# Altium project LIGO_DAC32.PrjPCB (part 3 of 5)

## Sheet LD32_XADC.SchDoc: XADC
size B; SheetNumber: 10; SheetTotal: 17; SPICEModelCacheGFFRXQKT: <root> / <DocumentId>GFFRXQKT</DocumentId> / <CacheFrame Number="0"> / <Model Name="op284f" Kind="CKT"> / <Text>* OP284F SPICE Macro-model              11/95 / Rev. B / *                                       ARG / ADSC / * / * Revision History: / * / *     Rev. B / * Changed the short-circuit output current limit from +/- 7.5mA / * to +/- 6.5mA to reflect final data sheet limits. / * / * Changed Vos spec to conform to final data sheet value of / * 125uV, up from 50uV. / * / * / * This version of the OP284 model simulates the worst-case / * parameters of the 'F' grade.  The worst-case parameters / * used correspond to those in the data sheet. / * / * Copyright 1993 by Analog Devices / * / * Refer to "README.DOC" file for License Statement. Use of this model / * indicates your acceptance of the terms and provisions in the License / * Statement. / * / * Node assignments / *                non-inverting input / *                ¦   inverting input / *                ¦   ¦   positive supply / *                ¦   ¦   ¦   negative supply / *                ¦   ¦   ¦   ¦   output / *                ¦   ¦   ¦   ¦   ¦ / .SUBCKT OP284F   1   2   99  50  45 / * / * INPUT STAGE / * / Q1   5    2    3    QIN 1 / Q2   6    11   3    QIN 1 / Q3   7    2    4    QIP 1 / Q4   8    11   4    QIP 1 / DC1  2    11   DC / DC2  11   2    DC / Q5   4    9    99   QIP 1 / Q6   9    9    99   QIP 1 / Q7   3    10   50   QIN 1 / Q8   10   10   50   QIN 1 / R1   99   5    4E3 / R2   99   6    4E3 / R3   7    50   4E3 / R4   8    50   4E3 / IREF 9    10   50.5E-6 / EOS  1    11   POLY(2) (22,98) (14,98) -125E-6 501.2E-3 1 / IOS  2    1    25E-9 / CIN  1    2    2E-12 / GN1  98   1    17 98 1E-3 / GN2  98   2    23 98 1E-3 / * / * VOLTAGE NOISE SOURCE WITH FLICKER NOISE / * / VN1  13   98   DC 2 / VN2  98   15   DC 2 / DN1  13   14   DEN / DN2  14   15   DEN / * / * CURRENT NOISE SOURCE WITH FLICKER NOISE / * / VN3  16   98   DC 2 / VN4  98   18   DC 2 / DN3  16   17   DIN / DN4  17   18   DIN / * / * 2ND CURRENT NOISE SOURCE WITH FLICKER NOISE / * / VN5  19   98   DC 2 / VN6  98   24   DC 2 / DN5  19   23   DIN / DN6  23   24   DIN / * / * GAIN STAGE / * / EREF 98   0    POLY(2) (99,0) (50,0) 0 0.5 0.5 / G1   98   20   POLY(2) (6,5) (8,7) 0 0.5E-3 0.5E-3 / R9   20   98   1E3 / * / * COMMON MODE STAGE WITH ZERO AT 5KHZ / * / ECM  98   21   POLY(2) (1,98) (2,98) 0 0.5 0.5 / R10  21   22   1 / R11  22   98   100E-6 / C4   21   22   31.756E-6 / * / * NEGATIVE ZERO AT 20MHZ / * / E1   27   98   20 98 1 / R17  27   28   1 / R18  28   98   1E-6 / C8   25   26   7.958E-9 / ENZ  25   98   27 28 1 / VNZ  26   98   DC 0 / FNZ  27   28   VNZ -1 / * / * POLE AT 40MHZ / * / G4   98   29   28 98 1E6 / R19  29   98   1 / C9   29   98   3.979E-9 / * / * POLE AT 40MHZ / * / G5   98   30   29 98 1 / R20  30   98   1 / C10  30   98   3.979E-9 / * / * OUTUT STAGE / * / ISY  99   50   0.526E-3 / GIN  50   31   POLY(1) (30,98) 0.862574E-6 511.855E-6 / RIN  31   50   2.75E6 / VB   99   32   0.7 / Q11  32   31   33   QON 1 / R21  33   34   4.5E3 / I1   34   50   50E-6 / R22  99   35   6E3 / Q12  36   36   35   QOP 1 / I2   36   50   50E-6 / R23  99   37   2.6E3 / R24  34   38   5E3 / Q13  39   36   37   QOP 1 / Q14  39   38   40   QON 1.5 / R25  40   50   40 / Q15  39   39   41   QON 1 / R26  41   42   1E3 / R27  99   43   220 / Q16  44   44   43   QOP 1.5 / Q17  44   39   42   QON 1 / R28  42   50   2E3 / VSCP 99   97   DC 0 / FSCP 46   99   VSCP 1 / RSCP 46   99   125 / Q20  44   46   99   QOP 1 / Q18  45   44   97   QOP 4.5 / Q19  45   34   51   QON 4.5 / VSCN 51   50   DC 0 / FSCN 50   47   VSCN 1 / RSCN 47   50   122 / Q21  34   47   50   QON 1 / CC2  31   45   20E-12 / CF1  31   34   15E-12 / CF2  31   42   15E-12 / CO1  34   45   15E-12 / CO2  42   45   5E-12 / D3   45   99   DX / D4   50   45   DX / .MODEL DC D(IS=130E-21) / .MODEL DX D() / .MODEL DEN D(RS=100 KF=12E-15 AF=1) / .MODEL DIN D(RS=5.358 KF=56E-15 AF=1) / .MODEL QIN NPN(BF=250 VA=200 IS=0.5E-16) / .MODEL QIP PNP(BF=60 VA=100 IS=0.5E-16) / .MODEL QON NPN(BF=200 VA=200 IS=0.5E-16 RC=140) / .MODEL QOP PNP(BF=200 VA=200 IS=0.5E-16 RC=210) / .ENDS</Text> / </Model> / </CacheFrame> / </root>
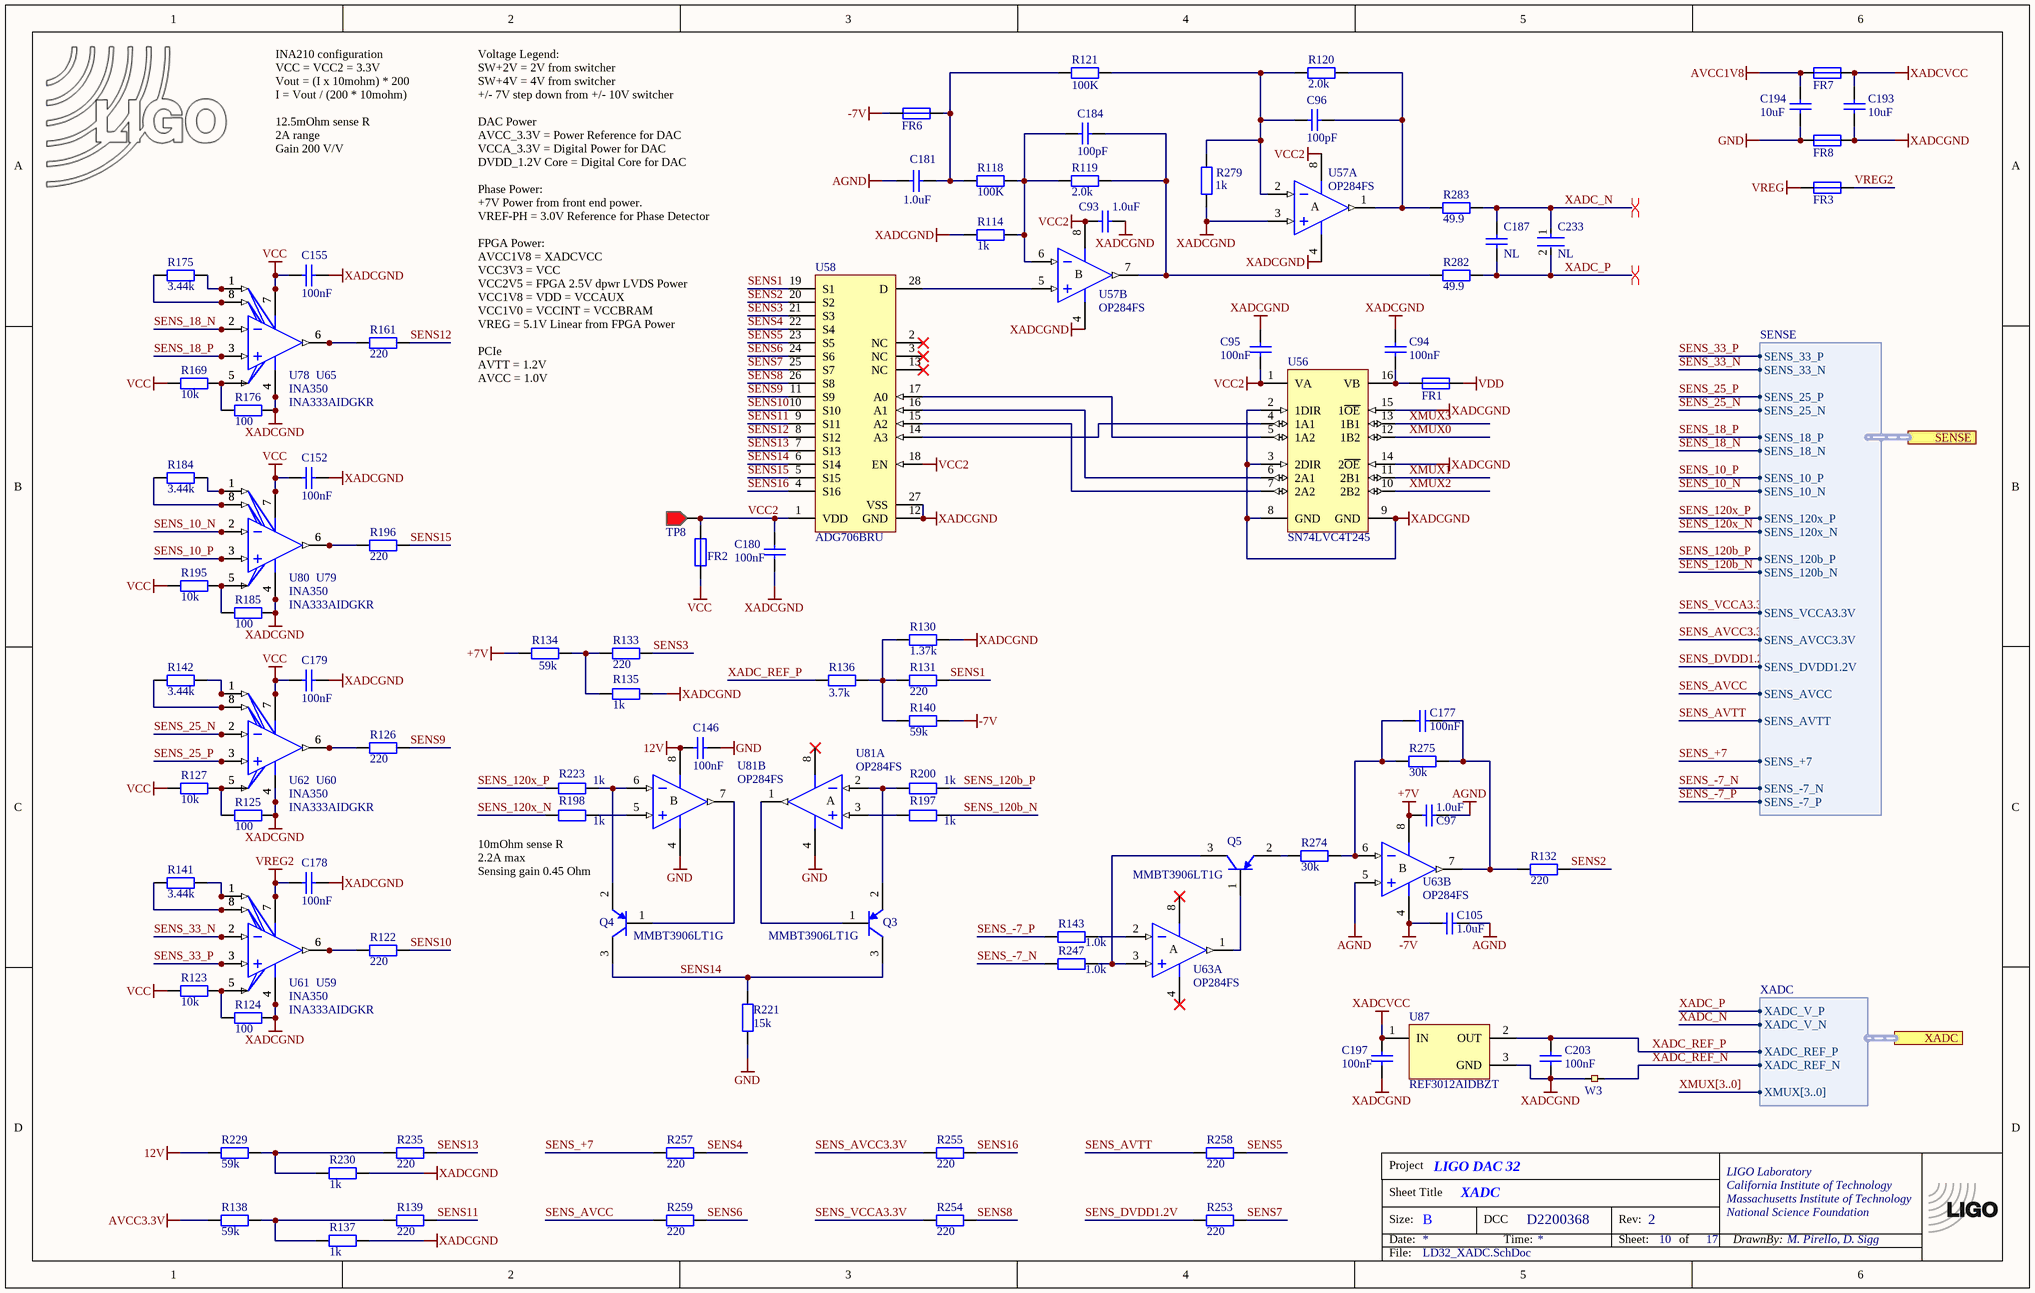
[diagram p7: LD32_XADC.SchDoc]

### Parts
(Parts that share a designator on the sheet are numbered #1, #2 ... from top to bottom, then left to right.)
*  TitleBlock  (value not drawn)  (graphical)
C93  1.0uF  [CC1005-0402]
C94  100nF  [CC1005-0402]
C95  100nF  [CC1005-0402]
C96  100pF  [CC1005-0402]
C97  1.0uF  [CC1608-0603]
C105  1.0uF  [CC1608-0603]
C146  100nF  [CC1005-0402]
C152  100nF  [CC1608-0603]
C155  100nF  [CC1608-0603]
C177  100nF  [CC1005-0402]
C178  100nF  [CC1608-0603]
C179  100nF  [CC1608-0603]
C180  100nF  [CC1005-0402]
C181  1.0uF  [CC1005-0402]
C184  100pF  [CC1005-0402]
C187  NL  [CC1005-0402]
C193  10uF  [CC2013-0805]
C194  10uF  [CC2013-0805]
C197  100nF  [CC1005-0402]
C203  100nF  [CC1005-0402]
C233  NL  [FP-CL03-IPC_B]
FR1  BLM31PG121  [CC3216-1206]  (value not drawn)
FR2  BLM31PG121  [CC3216-1206]  (value not drawn)
FR3  BLM31PG121  [CC3216-1206]  (value not drawn)
FR6  BLM31PG121  [CC3216-1206]  (value not drawn)
FR7  BLM31PG121  [CC3216-1206]  (value not drawn)
FR8  BLM31PG121  [CC3216-1206]  (value not drawn)
LOGO4#1  LIGO logo  [LIGO_LOGO]  (value not drawn)  (graphical)
Q3  MMBT3906LT1G  [ONSC-SOT-23-3-318-08_V]
Q4  MMBT3906LT1G  [ONSC-SOT-23-3-318-08_V]
Q5  MMBT3906LT1G  [ONSC-SOT-23-3-318-08_V]
R114  1k  [CR1608-0603]
R118  100K  [CR1005-0402]
R119  2.0k  [CR1005-0402]
R120  2.0k  [CR1005-0402]
R121  100K  [CR1005-0402]
R122  220  [CR1608-0603]
R123  10k  [CR1608-0603]
R124  100  [CR1608-0603]
R125  100  [CR1608-0603]
R126  220  [CR1608-0603]
R127  10k  [CR1608-0603]
R130  1.37k  [CR1608-0603]
R131  220  [CR1608-0603]
R132  220  [CR1608-0603]
R133  220  [CR1608-0603]
R134  59k  [CR1608-0603]
R135  1k  [CR1608-0603]
R136  3.7k  [CR1608-0603]
R137  1k  [CR1608-0603]
R138  59k  [CR1608-0603]
R139  220  [CR1608-0603]
R140  59k  [CR1608-0603]
R141  3.44k  [CR1608-0603]
R142  3.44k  [CR1608-0603]
R143  1.0k  [CR1005-0402]
R161  220  [CR1608-0603]
R169  10k  [CR1608-0603]
R175  3.44k  [CR1608-0603]
R176  100  [CR1608-0603]
R184  3.44k  [CR1608-0603]
R185  100  [CR1608-0603]
R195  10k  [CR1608-0603]
R196  220  [CR1608-0603]
R197  1k  [CR0603-0201]
R198  1k  [CR0603-0201]
R200  1k  [CR0603-0201]
R221  15k  [CR1608-0603]
R223  1k  [CR0603-0201]
R229  59k  [CR1608-0603]
R230  1k  [CR1608-0603]
R235  220  [CR1608-0603]
R247  1.0k  [CR1005-0402]
R253  220  [CR1608-0603]
R254  220  [CR1608-0603]
R255  220  [CR1608-0603]
R257  220  [CR1608-0603]
R258  220  [CR1608-0603]
R259  220  [CR1608-0603]
R274  30k  [CR1005-0402]
R275  30k  [CR1005-0402]
R279  1k  [CR1608-0603]
R282  49.9  [CR1005-0402]
R283  49.9  [CR1005-0402]
TP8  Testpoint  [TP1-RED]  (value not drawn)
U56  SN74LVC4T245  [TSSOP16]
U57  OP284FS  [SO-8_N]  (parts A,B of 2)
U58  ADG706BRU  [ADI-RU-28_M]
U59  INA333AIDGKR  [DGK0008A_N]
U60  INA333AIDGKR  [DGK0008A_N]
U61  INA350  [FP-RJ-8-IPC_B]
U62  INA350  [FP-RJ-8-IPC_B]
U63  OP284FS  [SO-8_N]  (parts A,B of 2)
U65  INA333AIDGKR  [DGK0008A_N]
U78  INA350  [FP-RJ-8-IPC_B]
U79  INA333AIDGKR  [DGK0008A_N]
U80  INA350  [FP-RJ-8-IPC_B]
U81  OP284FS  [SO-8_N]  (parts A,B of 2)
U87  REF3012AIDBZT  [DBZ0003A_L]
W3  NL  [NETTIE1_SMDTOP]  (value not drawn)  (net tie, no BOM)

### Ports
SENSE (harness SENSE), XADC (harness XADC)

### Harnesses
XADC: XADC_REF_P, XADC_V_N, XADC_V_P, XMUX[3..0], XADC_REF_N
SENSE: SENS_33_P, SENS_33_N, SENS_25_P, SENS_25_N, SENS_18_P, SENS_18_N, SENS_10_P, SENS_10_N, SENS_120x_P, SENS_120x_N, SENS_120b_P, SENS_120b_N, SENS_VCCA3.3V, SENS_AVCC3.3V, SENS_DVDD1.2V, SENS_+7, SENS_-7_P, SENS_AVTT, SENS_AVCC, SENS_-7_N

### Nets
12V: C146.1 R229.1 U81.8(V+)
+7V: C97.2 R134.1 U63.8(V+)
-7V: C105.2 FR6.1 R140.2 R143.1 U63.4(V-) ; port SENSE.SENS_-7_P  [also labelled SENS_-7_P]
AGND: C97.1 C105.1 C181.1 U63.5(IN+)
AVCC1V8: C194.1 FR7.1
AVCC3.3V: R138.1
GND: C146.2 C194.2 FR8.1 R221.1 U81.4(V-)
SENS_10_N: U79.2(VIN-) U80.2(IN+) ; port SENSE.SENS_10_N  [project net VCC1V0]
SENS_18_N: FR1.2 U65.2(VIN-) U78.2(IN+) ; port SENSE.SENS_18_N  [also labelled VDD]  [project net VCCAUX]
SENS_25_N: U60.2(VIN-) U62.2(IN+) ; port SENSE.SENS_25_N  [project net VCC2V5]
VCC: C152.1 C155.1 C179.1 FR2.1 R123.1 R127.1 R169.1 R195.1 U59.2(VIN-) U60.7(V+) U61.2(IN+) U62.7(V+) U65.7(V+) U78.7(V+) U79.7(V+) U80.7(V+) ; port SENSE.SENS_33_N  [also labelled SENS_33_N]
VCC2: C93.1 C95.2 C180.1 FR2.2 TP8.1 U56.1(VA) U57.8(V+) U58.1(VDD) U58.18(EN)
VREG: FR3.1
VREG2: C178.1 FR3.2 U59.7(V+) U61.7(V+)
XADCGND: C93.2 C94.1 C95.1 C152.2 C155.2 C178.2 C179.2 C180.2 C193.2 C197.2 C203.2 FR8.2 R114.1 R124.2 R125.2 R130.2 R135.2 R137.2 R176.2 R185.2 R230.2 R279.1 U56.2(1DIR) U56.3(2DIR) U56.8(GND) U56.9(GND) U56.14(2~{OE}) U56.15(1~{OE}) U57.3(IN+) U57.4(V-) U58.12(GND) U58.27(VSS) U59.4(V-) U60.4(V-) U61.4(V-) U62.4(V-) U65.4(V-) U78.4(V-) U79.4(V-) U80.4(V-) U87.3(GND) W3.1
XADCVCC: C193.1 C197.1 FR7.2 U87.1(IN)
SENS1: R131.2 U58.19(S1)
SENS2: R132.2 U58.20(S2)
SENS3: R133.2 U58.21(S3)
SENS4: R257.2 U58.22(S4)
SENS5: R258.2 U58.23(S5)
SENS6: R259.2 U58.24(S6)
SENS7: R253.2 U58.25(S7)
SENS8: R254.2 U58.26(S8)
SENS9: R126.2 U58.11(S9)
SENS10: R122.2 U58.10(S10)
SENS11: R139.2 U58.9(S11)
SENS12: R161.2 U58.8(S12)
SENS13: R235.2 U58.7(S13)
SENS14: Q3.3(C) Q4.3(C) R221.2 U58.6(S14)
SENS15: R196.2 U58.5(S15)
SENS16: R255.2 U58.4(S16)
SENS_10_P: U79.3(VIN+) U80.3(IN-) ; port SENSE.SENS_10_P  [project net SENSE.SENS_10_P]
SENS_18_P: U65.3(VIN+) U78.3(IN-) ; port SENSE.SENS_18_P  [project net SENSE.SENS_18_P]
SENS_25_P: U60.3(VIN+) U62.3(IN-) ; port SENSE.SENS_25_P  [project net SENSE.SENS_25_P]
SENS_33_P: U59.3(VIN+) U61.3(IN-) ; port SENSE.SENS_33_P  [project net SENSE.SENS_33_P]
SENS_120b_N: R197.2 ; port SENSE.SENS_120b_N  [project net SENSE.SENS_120b_N]
SENS_120b_P: R200.2 ; port SENSE.SENS_120b_P  [project net SENSE.SENS_120b_P]
SENS_120x_N: R198.1 ; port SENSE.SENS_120x_N  [project net SENSE.SENS_120x_N]
SENS_120x_P: R223.1 ; port SENSE.SENS_120x_P  [project net SENSE.SENS_120x_P]
SENS_+7: R257.1 ; port SENSE.SENS_+7  [project net SENSE.SENS_+7]
SENS_-7_N: R247.1 ; port SENSE.SENS_-7_N  [project net SENSE.SENS_-7_N]
SENS_AVCC: R259.1 ; port SENSE.SENS_AVCC  [project net SENSE.SENS_AVCC]
SENS_AVCC3.3V: R255.1 ; port SENSE.SENS_AVCC3.3V  [project net SENSE.SENS_AVCC3.3V]
SENS_AVTT: R258.1 ; port SENSE.SENS_AVTT  [project net SENSE.SENS_AVTT]
SENS_DVDD1.2V: R253.1 ; port SENSE.SENS_DVDD1.2V  [project net SENSE.SENS_DVDD1.2V]
SENS_VCCA3.3V: R254.1 ; port SENSE.SENS_VCCA3.3V  [project net SENSE.SENS_VCCA3.3V]
XADC_N: C187.2 C233.1 R283.2 ; port XADC.XADC_V_N
XADC_P: C187.1 C233.2 R282.2 ; port XADC.XADC_V_P
XADC_REF_N: W3.2 ; port XADC.XADC_REF_N
XADC_REF_P: C203.1 R136.1 U87.2(OUT) ; port XADC.XADC_REF_P
XMUX0: U56.12(1B2)
XMUX1: U56.11(2B1)
XMUX2: U56.10(2B2)
XMUX3: U56.13(1B1)
NetC94_2: C94.2 FR1.1 U56.16(VB)
NetC96_1: C96.1 R120.2 R283.1 U57.1(OUT)
NetC96_2: C96.2 R120.1 R121.2 R279.2 U57.2(IN-)
NetC177_1: C177.1 R132.1 R275.2 U63.7(OUT)
NetC177_2: C177.2 R274.2 R275.1 U63.6(IN-)
NetC181_2: C181.2 FR6.2 R118.1 R121.1
NetC184_1: C184.1 R119.2 R282.1 U57.7(OUT)
NetC184_2: C184.2 R114.2 R118.2 R119.1 U57.6(IN-)
NetQ3_1: Q3.1(B) U81.1(OUT)
NetQ3_2: Q3.2(E) R200.1 U81.2(IN-)
NetQ4_1: Q4.1(B) U81.7(OUT)
NetQ4_2: Q4.2(E) R223.2 U81.6(IN-)
NetQ5_1: Q5.1(B) U63.1(OUT)
NetQ5_2: Q5.2(E) R274.1
NetQ5_3: Q5.3(C) R247.2 U63.3(IN+)
NetR122_1: R122.1 U59.6(VOUT) U61.6(OUT)
NetR123_2: R123.2 R124.1 U59.5(REF) U61.5(REF)
NetR125_1: R125.1 R127.2 U60.5(REF) U62.5(REF)
NetR126_1: R126.1 U60.6(VOUT) U62.6(OUT)
NetR130_1: R130.1 R131.1 R136.2 R140.1
NetR133_1: R133.1 R134.2 R135.1
NetR137_1: R137.1 R138.2 R139.1
NetR141_1: R141.1 U59.8(RG) U61.8(!SHDN)
NetR141_2: R141.2 U59.1(RG) U61.1(GS)
NetR142_1: R142.1 U60.8(RG) U62.8(!SHDN)
NetR142_2: R142.2 U60.1(RG) U62.1(GS)
NetR143_2: R143.2 U63.2(IN-)
NetR161_1: R161.1 U65.6(VOUT) U78.6(OUT)
NetR169_2: R169.2 R176.1 U65.5(REF) U78.5(REF)
NetR175_1: R175.1 U65.8(RG) U78.8(!SHDN)
NetR175_2: R175.2 U65.1(RG) U78.1(GS)
NetR184_1: R184.1 U79.8(RG) U80.8(!SHDN)
NetR184_2: R184.2 U79.1(RG) U80.1(GS)
NetR185_1: R185.1 R195.2 U79.5(REF) U80.5(REF)
NetR196_1: R196.1 U79.6(VOUT) U80.6(OUT)
NetR197_1: R197.1 U81.3(IN+)
NetR198_2: R198.2 U81.5(IN+)
NetR229_2: R229.2 R230.1 R235.1
NetU56_4: U56.4(1A1) U58.14(A3)
NetU56_5: U56.5(1A2) U58.17(A0)
NetU56_6: U56.6(2A1) U58.16(A1)
NetU56_7: U56.7(2A2) U58.15(A2)
NetU57_5: U57.5(IN+) U58.28(D)

Not connected (* = marked no-connect by the designer): U58 2(NC)* 3(NC)* 13(NC)*

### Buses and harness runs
bus XMUX[3..0]

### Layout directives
differential pair: XADC_N, XADC_P

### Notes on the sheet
- 12.5mOhm sense R
  2A range
  Gain 200 V/V
- INA210 configuration
  VCC = VCC2 = 3.3V
  Vout = (I x 10mohm) * 200
  I = Vout / (200 * 10mohm)
- Voltage Legend:
  SW+2V = 2V from switcher
  SW+4V = 4V from switcher
  +/- 7V step down from +/- 10V switcher
  DAC Power
  AVCC_3.3V = Power Reference for DAC
  VCCA_3.3V = Digital Power for DAC
  DVDD_1.2V Core = Digital Core for DAC
  Phase Power:
  +7V Power from front end power.
  VREF-PH = 3.0V Reference for Phase Detector
  FPGA Power:
  AVCC1V8 = XADCVCC
  VCC3V3 = VCC
  VCC2V5 = FPGA 2.5V dpwr LVDS Power
  VCC1V8 = VDD = VCCAUX
  VCC1V0 = VCCINT = VCCBRAM
  VREG = 5.1V Linear from FPGA Power
  PCIe
  AVTT = 1.2V
  AVCC = 1.0V
- 10mOhm sense R
  2.2A max
  Sensing gain 0.45 Ohm

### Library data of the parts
C93 C181 = ChipCap: C0402 1.0uF; Part Number: C0402C105K4PACTU
C94 C95 C146 C177 C180 C197 C203 = ChipCap: C0402 0.1uF; Part Number: CL05B104KA5NNNC
C96 C184 = ChipCap: C0402 0.1nF; Part Number: 04025A101JAT2A
C97 C105 = ChipCap: C0603 1.0uF; Part Number: CL10B105KA8NNNC
C152 C155 C178 C179 = ChipCap: C0603 0.1uF; Part Number: CL10B104KB8NNNC
C187 = ChipCap
C193 C194 = ChipCap: C0805 10uF; Part Number: CL21A106KAYNNNG
C233 = CMP-2010-00306-2
FR1-FR3 FR6-FR8 = BLM31PG121SN1: ferrite bead, 120Ohm at 100MHz, 1206; Part Number: BLM31PG121SN1L
LOGO4#1 = LIGO_logo
Q3-Q5 = CMP-1048-00670-1: General Purpose Transistor, PNP Silicon, 3-Pin SOT-23, Pb-Free, Tape and Reel
R114 R135 R137 R230 R279 = ChipRes1: R0603 1k; Part Number: RR0816P-102-D
R118 R121 = ChipRes1: R0402 100k; Part Number: ERA-2AEB104X
R119 R120 = ChipRes1: R0402 2.0k; Part Number: ERA-2AEB202X
R122 R126 R131-R133 R139 R161 R196 R235 R253-R255 R257-R259 = ChipRes1: R0603 220; Part Number: ERA-3AEB221V
R123 R127 R169 R195 = ChipRes1: R0603 10k; Part Number: ERA-3AEB103V
R124 R125 R176 R185 = ChipRes1: R0603 100; Part Number: ERA-3AEB101V
R130 = ChipRes1: R0603 1.37k; Part Number: ERA-3AEB1371V
R134 R138 R229 = ChipRes1: R0603 59k; Part Number: ERA-3AEB5902V
R136 = ChipRes1: R0603 3.7k; Part Number: RN73H1JTTD3701B25
R140 = ChipRes1: R0603 59k; Part Number: ERA-2AEB5902X
R141 R142 R175 R184 = ChipRes1: R0603 3.44k; Part Number: TNPW06033K44BEEN
R143 R247 = ChipRes1: R0402 1.0k; Part Number: ERA-2AEB102X
R197 R198 R200 R223 = ChipRes1: R0201 1k; Part Number: ERA-1AEB102C
R221 = ChipRes1: R0603 15k; Part Number: ERA-3AEB153V
R274 R275 = ChipRes1: R0402 30k; Part Number: ERA-2AEB303X
R282 R283 = ChipRes1: R0402 49.9; Part Number: ERA-2AEB49R9X
TP8 = TP_POSITIVE: Testpoint, red; Part Number: Keystone / 5000
U56 = SN74LVC4T245: Quad-Bit Dual Supply Transceiver; Part Number: 296-18056-1-ND
U57 U63 U81 = OP284FS: Precision Rail-to-Rail Input and Output Operational Amplifier; Part Number: OP284FSZ-REEL7
U58 = CMP-0798-00217-1: 1.8 to 5.5 V / 2.5 V, CMOS Low-Voltage 2.5 Ohm, 16-Channel Multiplexer, -40 to 85 degC, 28-pin SOP (RU-28), Tube; Part Number: ADG706BRUZ-REEL7
U59 U60 U65 U79 = CMP-0944-00088-2: Low Power, Precision Instrumentation Amplifier, -40 to 125 degC, 8-pin SOP (DGK8), Green (RoHS & no Sb/Br); Part Number: INA333QDGKRQ1
U61 U62 U78 U80 = INA350: NL
U87 = CMP-0367-00158-2: 1.25 V, 50 ppm / degC, 50 uA Series (Bandgap) Voltage Reference, -40 to 125 degC, 3-pin SOT-23 (DBZ), Green (RoHS & no Sb/Br)
W3 = NetTie1_small

## Sheet LD32_FLASH.SchDoc: JTAG & SPI Flash
size B; SheetNumber: 9; SheetTotal: 17
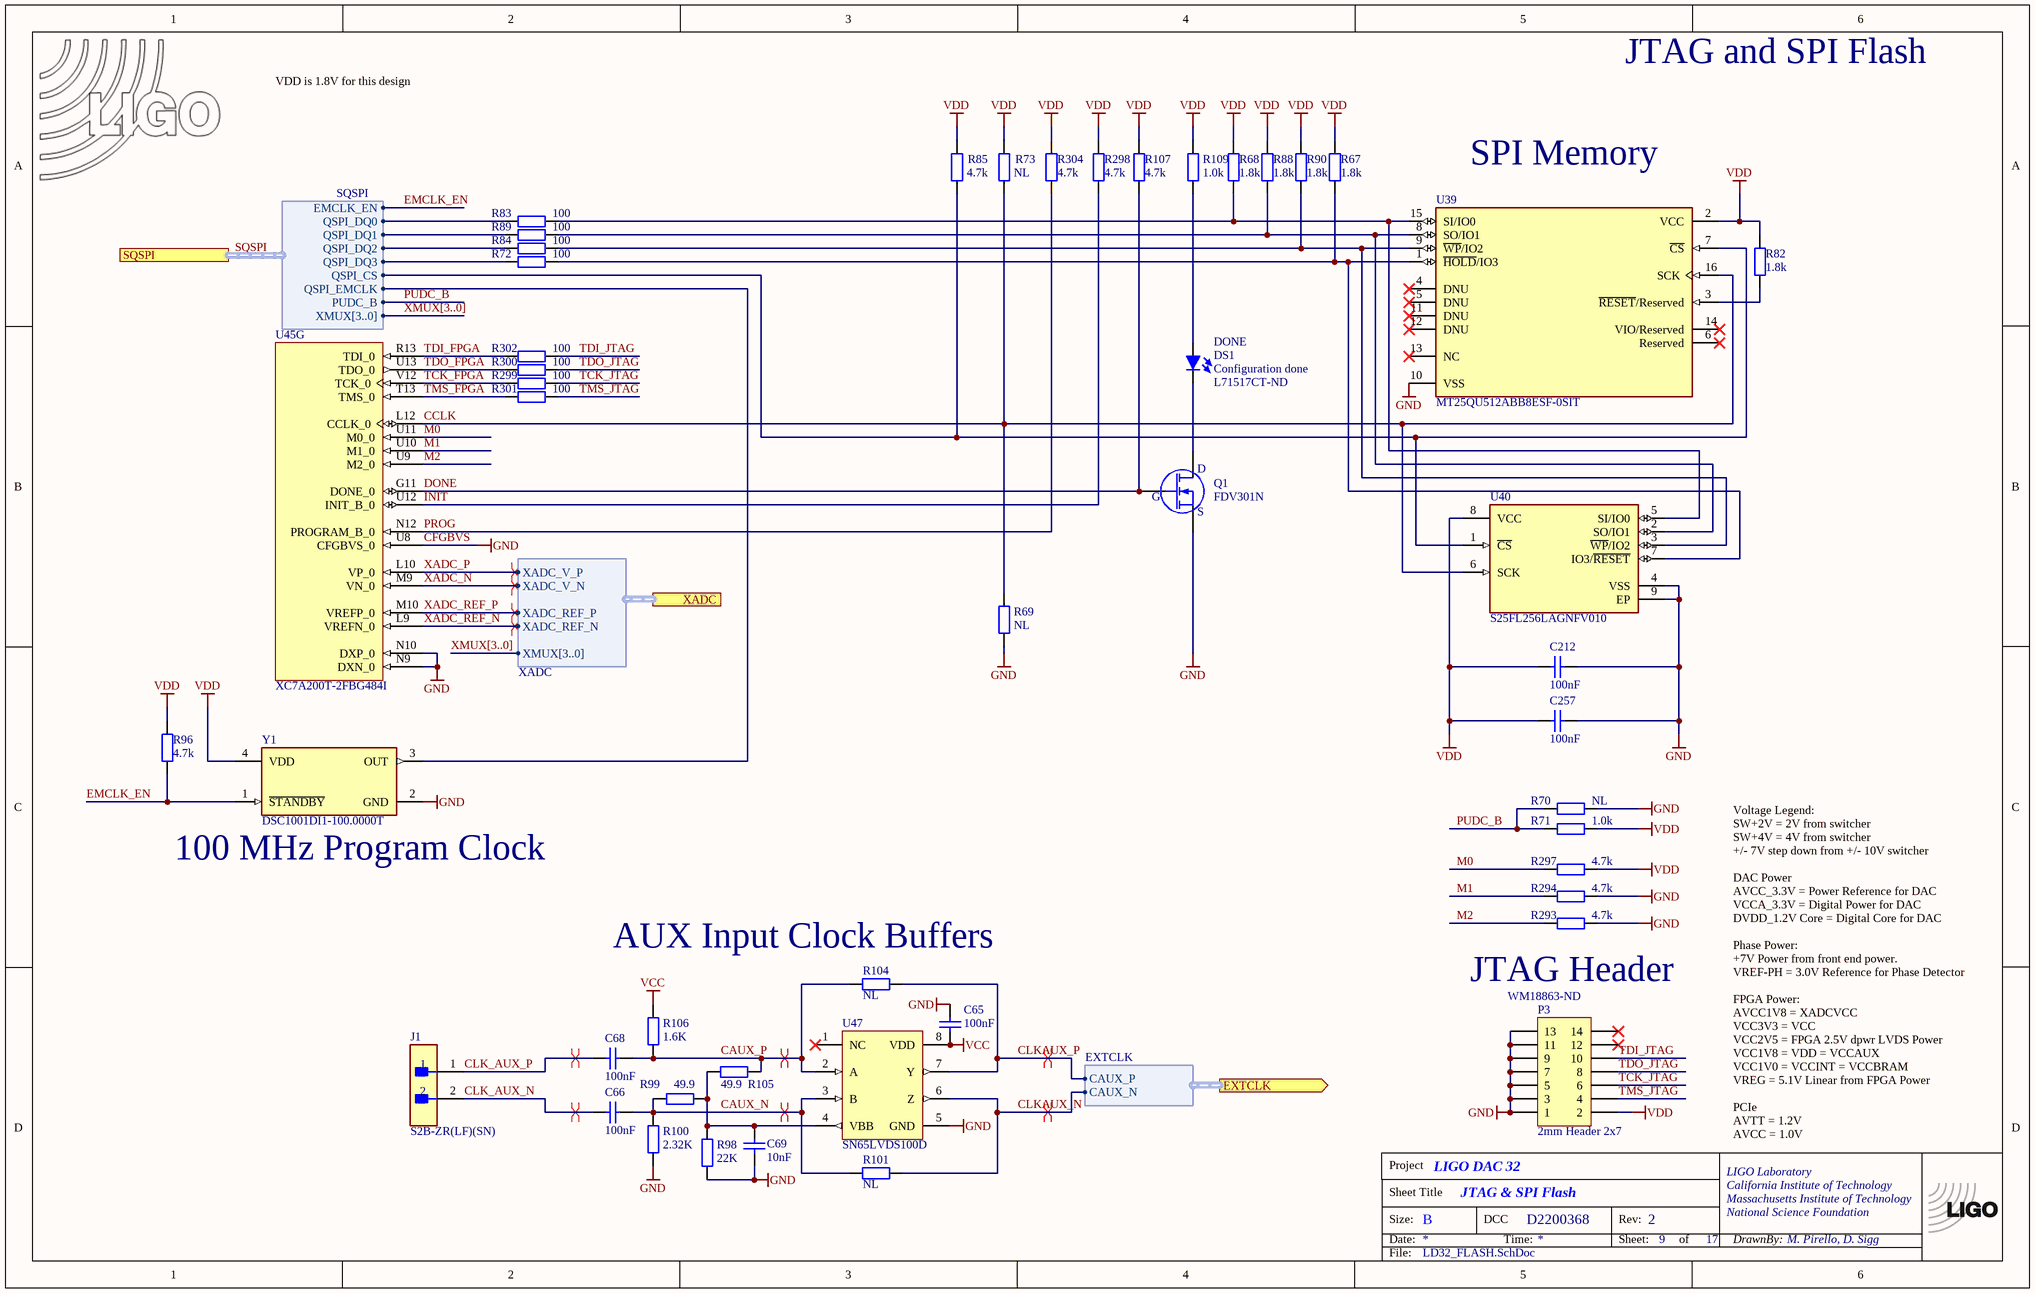
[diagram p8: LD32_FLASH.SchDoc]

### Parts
(Parts that share a designator on the sheet are numbered #1, #2 ... from top to bottom, then left to right.)
*?#5  TitleBlock  (value not drawn)  (graphical)
C65  100nF  [CC1608-0603]
C66  100nF  [CC1005-0402]
C68  100nF  [CC1005-0402]
C69  10nF  [CC1005-0402]
C212  100nF  [CC1005-0402]
C257  100nF  [CC1005-0402]
DS1  DONE  Supplier Part Number 1: L71517CT-ND  [LED-0805]
J1  S2B-ZR(LF)(SN)  [FP-S2B-ZR_LF_SN-MFG]
LOGO3  LIGO logo  [LIGO_LOGO]  (value not drawn)  (graphical)
P3  2mm Header 2x7  Supplier Part Number 1: WM18863-ND  [2MM_HDR2X7_RA]
Q1  FDV301N  [SO-G3/C2.25]
R67  1.8k  [CR1005-0402]
R68  1.8k  [CR1005-0402]
R69  NL  [CR1005-0402]
R70  NL  [CR1005-0402]
R71  1.0k  [CR1005-0402]
R72  100  [CR1005-0402]
R73  NL  [CR1005-0402]
R82  1.8k  [CR1005-0402]
R83  100  [CR1005-0402]
R84  100  [CR1005-0402]
R85  4.7k  [CR1005-0402]
R88  1.8k  [CR1005-0402]
R89  100  [CR1005-0402]
R90  1.8k  [CR1005-0402]
R96  4.7k  [CR1005-0402]
R98  22K  [CR1005-0402]
R99  49.9  [CR1005-0402]
R100  2.32K  [CR1005-0402]
R101  NL  [CR1005-0402]
R104  NL  [CR1005-0402]
R105  49.9  [CR1005-0402]
R106  1.6K  [CR1005-0402]
R107  4.7k  [CR1005-0402]
R109  1.0k  [CR1005-0402]
R293  4.7k  [CR1005-0402]
R294  4.7k  [CR1005-0402]
R297  4.7k  [CR1005-0402]
R298  4.7k  [CR1005-0402]
R299  100  [CR1005-0402]
R300  100  [CR1005-0402]
R301  100  [CR1005-0402]
R302  100  [CR1005-0402]
R304  4.7k  [CR1005-0402]
U39  MT25QU512ABB8ESF-0SIT  [FP-002-15547-MFG]
U40  S25FL256LAGNFV010  [FP-002-18827-MFG]
U45  XC7A200T-2FBG484I  [FBG484]  (part G of 11)
U47  SN65LVDS100D  [MSOP8]
Y1  DSC1001DI1-100.0000T  [FP-CDFN2520-4LD-PL-1-MFG]

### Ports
EXTCLK (out, harness EXTCLK), SQSPI (harness SQSPI), XADC (harness XADC)

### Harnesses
SQSPI: QSPI_DQ0, QSPI_DQ1, QSPI_DQ2, QSPI_DQ3, QSPI_CS, QSPI_EMCLK, PUDC_B, XMUX[3..0], EMCLK_EN
XADC: XADC_REF_P, XADC_V_N, XADC_V_P, XMUX[3..0], XADC_REF_N
EXTCLK: CAUX_P, CAUX_N

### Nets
GND: C65.1 C69.1 C212.1 C257.1 P3.1 P3.3 P3.5 P3.7 P3.9 P3.11 P3.13 Q1.2(S) R69.2 R70.2 R98.2 R100.2 R293.2 R294.2 U39.10(VSS) U40.4(VSS) U40.9(EP) U45.N9(DXN_0) U45.N10(DXP_0) U45.U8(CFGBVS_0) U47.5(GND) Y1.2(GND)  [also labelled CFGBVS]
VCC: C65.2 R106.1 U47.8(VDD)
VDD: C212.2 C257.2 P3.2 R67.2 R68.2 R71.2 R73.1 R82.2 R85.1 R88.2 R90.2 R96.1 R107.2 R109.1 R297.2 R298.2 R304.2 U39.2(VCC) U40.8(VCC) Y1.4(VDD)  [project net VCCAUX]
CAUX_N: C66.2 R99.2 R100.1 R101.1 U47.3(B)
CAUX_P: C68.2 R104.1 R105.1 R106.2 U47.2(A)
CCLK: R69.1 R73.2 U39.16(SCK) U40.6(SCK) U45.L12(CCLK_0)
CLK_AUX_N: C66.1 J1.2
CLK_AUX_P: C68.1 J1.1
CLKAUX_N: R101.2 U47.6(Z) ; port EXTCLK.CAUX_N  [project net EXTCLK.CAUX_N]
CLKAUX_P: R104.2 U47.7(Y) ; port EXTCLK.CAUX_P  [project net EXTCLK.CAUX_P]
DONE: Q1.1(G) R107.1 U45.G11(DONE_0)
EMCLK_EN: R96.2 Y1.1(~{STANDBY}) ; port SQSPI.EMCLK_EN  [project net SQSPI.EMCLK_EN]
INIT: R298.1 U45.U12(INIT_B_0)
M0: R297.1 U45.U11(M0_0)
M1: R294.1 U45.U10(M1_0)
M2: R293.1 U45.U9(M2_0)
PROG: R304.1 U45.N12(PROGRAM_B_0)
PUDC_B: R70.1 R71.1 ; port SQSPI.PUDC_B  [project net SQSPI.PUDC_B]
SQSPI.QSPI_CS: R85.2 U39.7(~{CS}) U40.1(~{CS}) ; port SQSPI.QSPI_CS
SQSPI.QSPI_DQ0: R83.2 ; port SQSPI.QSPI_DQ0
SQSPI.QSPI_DQ1: R89.2 ; port SQSPI.QSPI_DQ1
SQSPI.QSPI_DQ2: R84.2 ; port SQSPI.QSPI_DQ2
SQSPI.QSPI_DQ3: R72.2 ; port SQSPI.QSPI_DQ3
SQSPI.QSPI_EMCLK: Y1.3(OUT) ; port SQSPI.QSPI_EMCLK
TCK_FPGA: R299.2 U45.V12(TCK_0)
TCK_JTAG: P3.6 R299.1
TDI_FPGA: R302.2 U45.R13(TDI_0)
TDI_JTAG: P3.10 R302.1
TDO_FPGA: R300.2 U45.U13(TDO_0)
TDO_JTAG: P3.8 R300.1
TMS_FPGA: R301.2 U45.T13(TMS_0)
TMS_JTAG: P3.4 R301.1
XADC_N: U45.M9(VN_0) ; port XADC.XADC_V_N
XADC_P: U45.L10(VP_0) ; port XADC.XADC_V_P
XADC_REF_N: U45.L9(VREFN_0) ; port XADC.XADC_REF_N
XADC_REF_P: U45.M10(VREFP_0) ; port XADC.XADC_REF_P
NetC69_2: C69.2 R98.1 R99.1 R105.2 U47.4(VBB)
NetDS1_1: DS1.1(K) Q1.3(D)
NetDS1_2: DS1.2(A) R109.2
NetR67_1: R67.1 R72.1 U39.1(~{HOLD}/IO3) U40.7(IO3/~{RESET})
NetR68_1: R68.1 R83.1 U39.15(SI/IO0) U40.5(SI/IO0)
NetR82_1: R82.1 U39.3(~{RESET}/Reserved)
NetR84_1: R84.1 R90.1 U39.9(~{WP}/IO2) U40.3(~{WP}/IO2)
NetR88_1: R88.1 R89.1 U39.8(SO/IO1) U40.2(SO/IO1)

Not connected (* = marked no-connect by the designer): P3 12* 14*; U39 4(DNU)* 5(DNU)* 6(Reserved)* 11(DNU)* 12(DNU)* 13(NC)* 14(VIO/Reserved)*; U47 1(NC)*

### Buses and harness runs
bus XMUX[3..0]
harness SQSPI = port SQSPI

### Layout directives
differential pair: CAUX_N, CAUX_P, CLK_AUX_N, CLK_AUX_P, EXTCLK.CAUX_N, EXTCLK.CAUX_P, XADC_N, XADC_P, XADC_REF_N, XADC_REF_P

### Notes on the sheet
- JTAG and SPI Flash
- VDD is 1.8V for this design
- (near U39) SPI Memory
- (near DS1) Configuration done
- (near Y1) 100 MHz Program Clock
- (near R104) AUX Input Clock Buffers
- JTAG Header
- Voltage Legend:
  SW+2V = 2V from switcher
  SW+4V = 4V from switcher
  +/- 7V step down from +/- 10V switcher
  DAC Power
  AVCC_3.3V = Power Reference for DAC
  VCCA_3.3V = Digital Power for DAC
  DVDD_1.2V Core = Digital Core for DAC
  Phase Power:
  +7V Power from front end power.
  VREF-PH = 3.0V Reference for Phase Detector
  FPGA Power:
  AVCC1V8 = XADCVCC
  VCC3V3 = VCC
  VCC2V5 = FPGA 2.5V dpwr LVDS Power
  VCC1V8 = VDD = VCCAUX
  VCC1V0 = VCCINT = VCCBRAM
  VREG = 5.1V Linear from FPGA Power
  PCIe
  AVTT = 1.2V
  AVCC = 1.0V

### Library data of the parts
C65 = ChipCap: as C152 on sheet LD32_XADC
C66 C68 C212 C257 = ChipCap: as C94 on sheet LD32_XADC
C69 = ChipCap: C0402 0.01uF; Part Number: CC0402JRX7R9BB103
DS1 = LED: Panel mount LED
J1 = CMP-2000-07021-2: CONN HEADER R/A 2POS 1.5MM
LOGO3 = LIGO_logo
P3 = Xilinx_JTAG_Header: Xilinx JTAG header, 7-Pin, Dual row
Q1 = FDV301N: FDV301N, Digital FET, N-channel, SOT23; Part Number: FDV301NCT-ND
R67 R68 R82 R88 R90 = ChipRes1: R0402 1.8k; Part Number: RR05P1.8KDCT-ND
R69 R70 R73 R101 R104 = ChipRes1
R71 R109 = ChipRes1: R0402 1.0k; Part Number: ERA-2AEB102X
R72 R83 R84 R89 R299-R302 = ChipRes1: R0402 100; Part Number: RR0510P-101-D
R85 R96 R107 R293 R294 R297 R298 R304 = ChipRes1: R0402 4.7k; Part Number: ERA-2AED472X
R98 = ChipRes1: R0402 22k; Part Number: ERA-2AED223X
R99 R105 = ChipRes1: R0402 49.9; Part Number: ERA-2AEB49R9X
R100 = ChipRes1: R0402 2.32k; Part Number: ERA-2AEB2321X
R106 = ChipRes1: R0402 1.6k; Part Number: ERA-2AEB162X
U39 = CMP-12948-000005-1: IC FLASH 128M SPI 133MHZ 16SOIC
U40 = CMP-12948-000008-1: NL
U45 = CMP-0364-00012-3: Artix-7 FPGA, 285 User I/Os, 4 GTP, 484-Ball BGA, Speed Grade 2, Industrial Grade, Pb-Free
U47 = SN65LVDS100: DIFF TRANSLATOR; Part Number: SN65LVDS100DGKR
Y1 = CMP-06255-000005-1: MEMS OSC XO 100.0000MHZ CMOS SMD

## Sheet LD32_PHASE.SchDoc: VCO & Phase Detector
size B; SheetNumber: 2; SheetTotal: 17; SPICEModelCacheGRPSJKPR: <root> / <DocumentId>GRPSJKPR</DocumentId> / <CacheFrame Number="0"> / <Model Name="op284f" Kind="CKT"> / <Text>* OP284F SPICE Macro-model              11/95 / Rev. B / *                                       ARG / ADSC / * / * Revision History: / * / *     Rev. B / * Changed the short-circuit output current limit from +/- 7.5mA / * to +/- 6.5mA to reflect final data sheet limits. / * / * Changed Vos spec to conform to final data sheet value of / * 125uV, up from 50uV. / * / * / * This version of the OP284 model simulates the worst-case / * parameters of the 'F' grade.  The worst-case parameters / * used correspond to those in the data sheet. / * / * Copyright 1993 by Analog Devices / * / * Refer to "README.DOC" file for License Statement. Use of this model / * indicates your acceptance of the terms and provisions in the License / * Statement. / * / * Node assignments / *                non-inverting input / *                ¦   inverting input / *                ¦   ¦   positive supply / *                ¦   ¦   ¦   negative supply / *                ¦   ¦   ¦   ¦   output / *                ¦   ¦   ¦   ¦   ¦ / .SUBCKT OP284F   1   2   99  50  45 / * / * INPUT STAGE / * / Q1   5    2    3    QIN 1 / Q2   6    11   3    QIN 1 / Q3   7    2    4    QIP 1 / Q4   8    11   4    QIP 1 / DC1  2    11   DC / DC2  11   2    DC / Q5   4    9    99   QIP 1 / Q6   9    9    99   QIP 1 / Q7   3    10   50   QIN 1 / Q8   10   10   50   QIN 1 / R1   99   5    4E3 / R2   99   6    4E3 / R3   7    50   4E3 / R4   8    50   4E3 / IREF 9    10   50.5E-6 / EOS  1    11   POLY(2) (22,98) (14,98) -125E-6 501.2E-3 1 / IOS  2    1    25E-9 / CIN  1    2    2E-12 / GN1  98   1    17 98 1E-3 / GN2  98   2    23 98 1E-3 / * / * VOLTAGE NOISE SOURCE WITH FLICKER NOISE / * / VN1  13   98   DC 2 / VN2  98   15   DC 2 / DN1  13   14   DEN / DN2  14   15   DEN / * / * CURRENT NOISE SOURCE WITH FLICKER NOISE / * / VN3  16   98   DC 2 / VN4  98   18   DC 2 / DN3  16   17   DIN / DN4  17   18   DIN / * / * 2ND CURRENT NOISE SOURCE WITH FLICKER NOISE / * / VN5  19   98   DC 2 / VN6  98   24   DC 2 / DN5  19   23   DIN / DN6  23   24   DIN / * / * GAIN STAGE / * / EREF 98   0    POLY(2) (99,0) (50,0) 0 0.5 0.5 / G1   98   20   POLY(2) (6,5) (8,7) 0 0.5E-3 0.5E-3 / R9   20   98   1E3 / * / * COMMON MODE STAGE WITH ZERO AT 5KHZ / * / ECM  98   21   POLY(2) (1,98) (2,98) 0 0.5 0.5 / R10  21   22   1 / R11  22   98   100E-6 / C4   21   22   31.756E-6 / * / * NEGATIVE ZERO AT 20MHZ / * / E1   27   98   20 98 1 / R17  27   28   1 / R18  28   98   1E-6 / C8   25   26   7.958E-9 / ENZ  25   98   27 28 1 / VNZ  26   98   DC 0 / FNZ  27   28   VNZ -1 / * / * POLE AT 40MHZ / * / G4   98   29   28 98 1E6 / R19  29   98   1 / C9   29   98   3.979E-9 / * / * POLE AT 40MHZ / * / G5   98   30   29 98 1 / R20  30   98   1 / C10  30   98   3.979E-9 / * / * OUTUT STAGE / * / ISY  99   50   0.526E-3 / GIN  50   31   POLY(1) (30,98) 0.862574E-6 511.855E-6 / RIN  31   50   2.75E6 / VB   99   32   0.7 / Q11  32   31   33   QON 1 / R21  33   34   4.5E3 / I1   34   50   50E-6 / R22  99   35   6E3 / Q12  36   36   35   QOP 1 / I2   36   50   50E-6 / R23  99   37   2.6E3 / R24  34   38   5E3 / Q13  39   36   37   QOP 1 / Q14  39   38   40   QON 1.5 / R25  40   50   40 / Q15  39   39   41   QON 1 / R26  41   42   1E3 / R27  99   43   220 / Q16  44   44   43   QOP 1.5 / Q17  44   39   42   QON 1 / R28  42   50   2E3 / VSCP 99   97   DC 0 / FSCP 46   99   VSCP 1 / RSCP 46   99   125 / Q20  44   46   99   QOP 1 / Q18  45   44   97   QOP 4.5 / Q19  45   34   51   QON 4.5 / VSCN 51   50   DC 0 / FSCN 50   47   VSCN 1 / RSCN 47   50   122 / Q21  34   47   50   QON 1 / CC2  31   45   20E-12 / CF1  31   34   15E-12 / CF2  31   42   15E-12 / CO1  34   45   15E-12 / CO2  42   45   5E-12 / D3   45   99   DX / D4   50   45   DX / .MODEL DC D(IS=130E-21) / .MODEL DX D() / .MODEL DEN D(RS=100 KF=12E-15 AF=1) / .MODEL DIN D(RS=5.358 KF=56E-15 AF=1) / .MODEL QIN NPN(BF=250 VA=200 IS=0.5E-16) / .MODEL QIP PNP(BF=60 VA=100 IS=0.5E-16) / .MODEL QON NPN(BF=200 VA=200 IS=0.5E-16 RC=140) / .MODEL QOP PNP(BF=200 VA=200 IS=0.5E-16 RC=210) / .ENDS</Text> / </Model> / </CacheFrame> / </root>
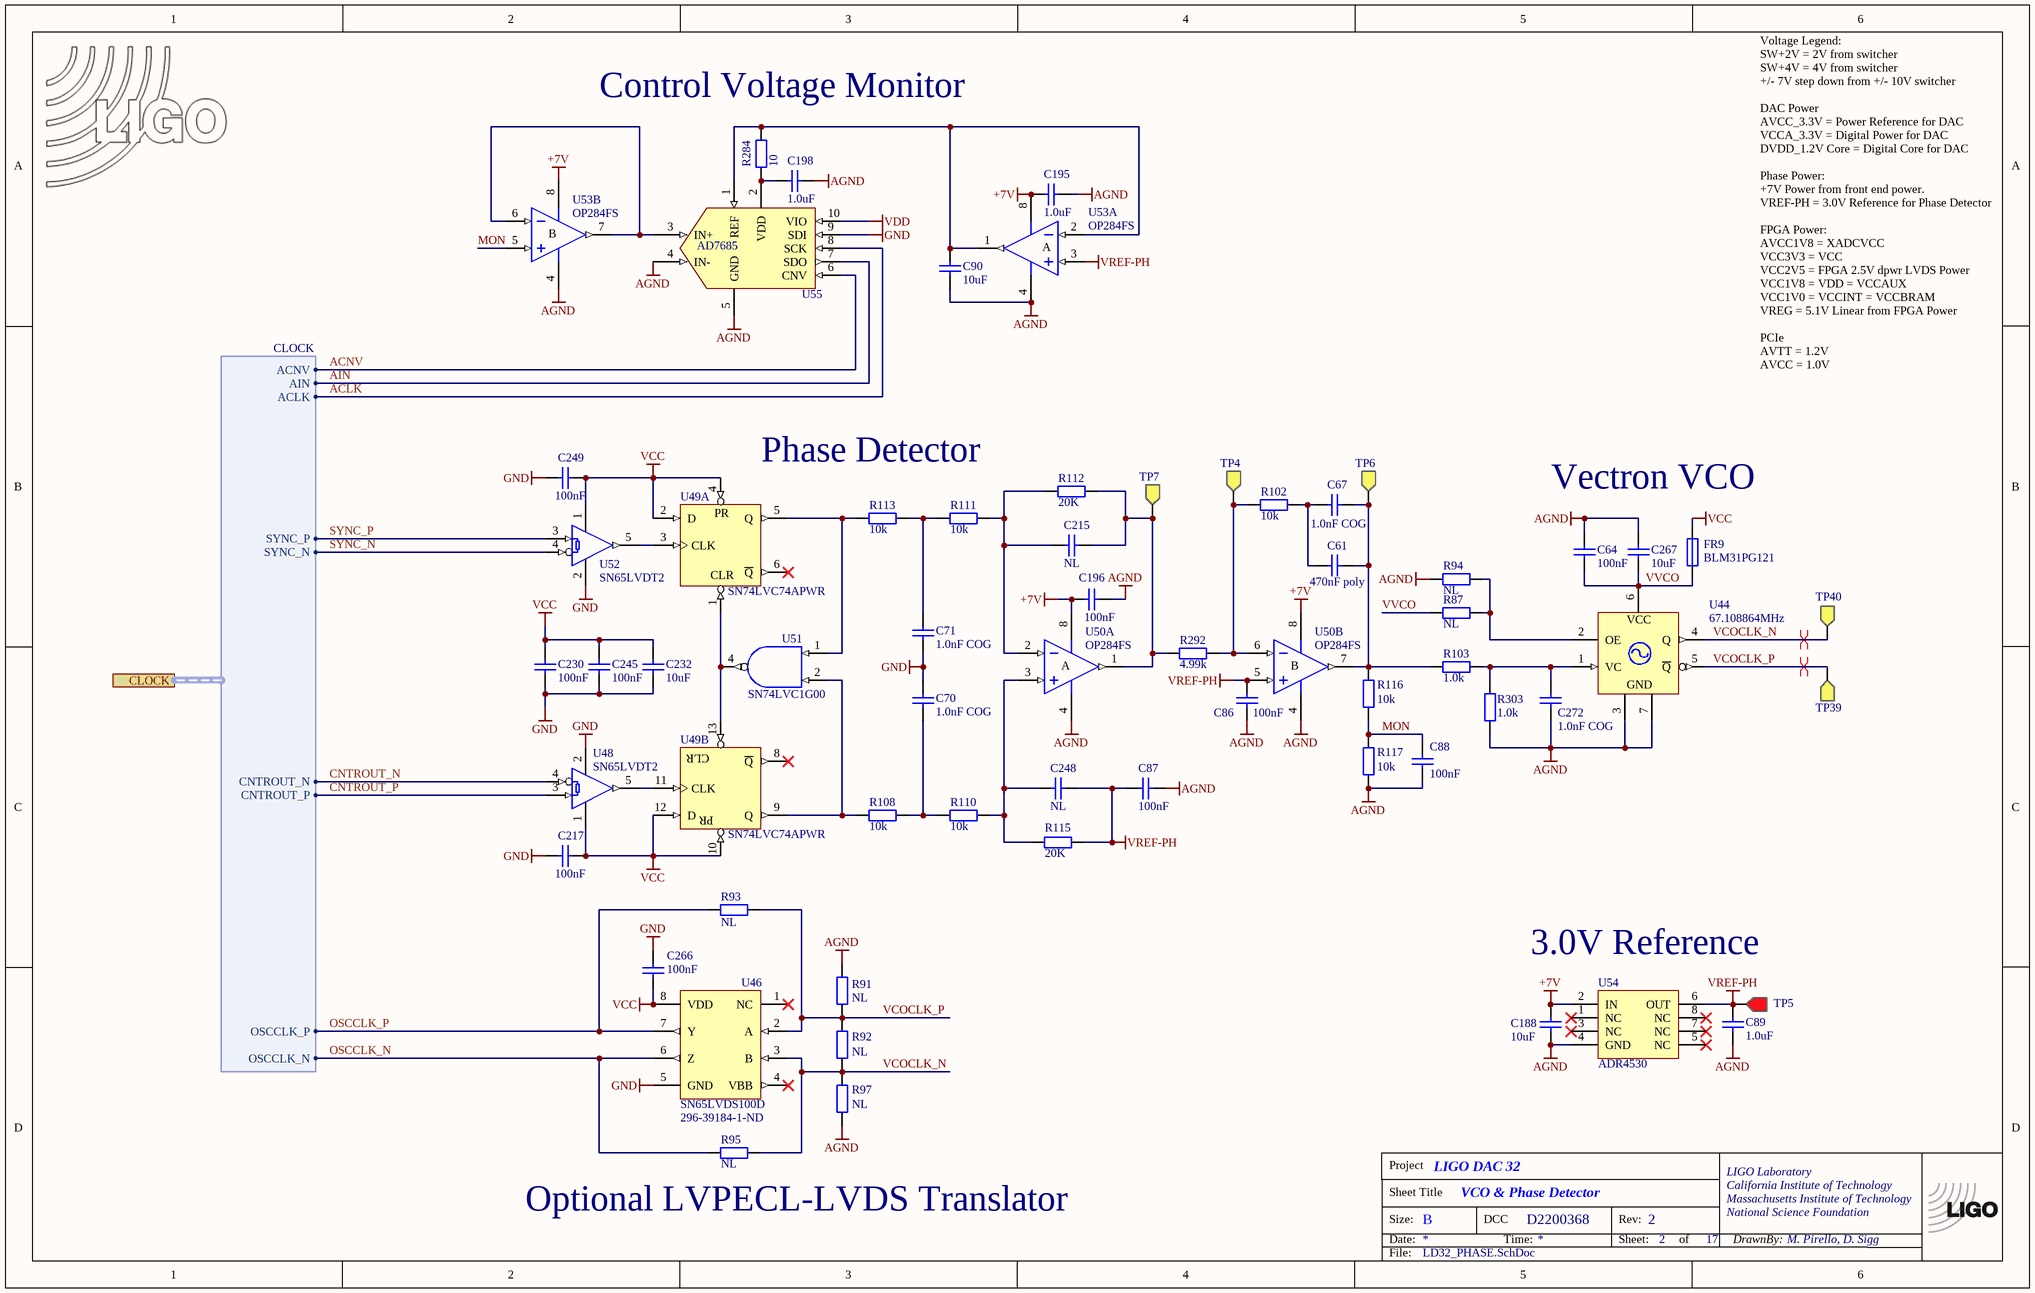
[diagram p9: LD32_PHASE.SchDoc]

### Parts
(Parts that share a designator on the sheet are numbered #1, #2 ... from top to bottom, then left to right.)
*?#6  TitleBlock  (value not drawn)  (graphical)
C61  470nF poly  [ECQPZ120060-5.0]
C64  100nF  [CC1005-0402]
C67  1.0nF COG  [CC1005-0402]
C70  1.0nF COG  [CC1005-0402]
C71  1.0nF COG  [CC1005-0402]
C86  100nF  [CC1005-0402]
C87  100nF  [CC1005-0402]
C88  100nF  [CC1005-0402]
C89  1.0uF  [CC1608-0603]
C90  10uF  [CC2013-0805]
C188  10uF  [CC2013-0805]
C195  1.0uF  [CC1608-0603]
C196  100nF  [CC1005-0402]
C198  1.0uF  [CC1608-0603]
C215  NL  [CC2013-0805]
C217  100nF  [CC1005-0402]
C230  100nF  [CC1005-0402]
C232  10uF  [CC2013-0805]
C245  100nF  [CC1005-0402]
C248  NL  [CC2013-0805]
C249  100nF  [CC1005-0402]
C266  100nF  [CC1005-0402]
C267  10uF  [CC2013-0805]
C272  1.0nF COG  [CC1005-0402]
FR9  BLM31PG121  [CC3216-1206]
LOGO2#1  LIGO logo  [LIGO_LOGO]  (value not drawn)  (graphical)
R87  NL  [CR1608-0603]
R91  NL  [CR1005-0402]
R92  NL  [CR1005-0402]
R93  NL  [CR1005-0402]
R94  NL  [CR1608-0603]
R95  NL  [CR1005-0402]
R97  NL  [CR1005-0402]
R102  10k  [CR1005-0402]
R103  1.0k  [CR1005-0402]
R108  10k  [CR1005-0402]
R110  10k  [CR1005-0402]
R111  10k  [CR1005-0402]
R112  20K  [CR1005-0402]
R113  10k  [CR1005-0402]
R115  20K  [CR1005-0402]
R116  10k  [CR1005-0402]
R117  10k  [CR1005-0402]
R284  10  [CR1005-0402]
R292  4.99k  [CR1005-0402]
R303  1.0k  [CR1005-0402]
TP4  Testpoint  [TP1-YLW]  (value not drawn)
TP5  Testpoint  [TP1-RED]  (value not drawn)
TP6  Testpoint  [TP1-YLW]  (value not drawn)
TP7  Testpoint  [TP1-YLW]  (value not drawn)
TP39  Testpoint  [TP2]  (value not drawn)
TP40  Testpoint  [TP2]  (value not drawn)
U44  67.108864MHz  [BomarSiTime]
U46  SN65LVDS100D  Supplier Part Number 1: 296-39184-1-ND  [MSOP8]
U48  SN65LVDT2  [SO-G5/E2.4]
U49  SN74LVC74APWR  [TSSOP14]  (parts A,B of 2)
U50  OP284FS  [SO-8_N]  (parts A,B of 2)
U51  SN74LVC1G00  [SO-G5/E2.4]
U52  SN65LVDT2  [SO-G5/E2.4]
U53  OP284FS  [SO-8_N]  (parts A,B of 2)
U54  ADR4530  [SO-G8]
U55  AD7685  [TSSO3x5-G10]

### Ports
CLOCK (harness CLOCK)

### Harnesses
CLOCK: OSCCLK_N, OSCCLK_P, CNTROUT_N, CNTROUT_P, SYNC_N, SYNC_P, ACLK, ACNV, AIN

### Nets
+7V: C188.1 C195.2 C196.2 U50.8(V+) U53.8(V+) U54.2(IN)
AGND: C64.1 C86.1 C87.1 C88.1 C89.1 C90.2 C188.2 C195.1 C196.1 C198.1 C267.1 C272.2 R91.1 R94.2 R97.2 R117.2 R303.2 U44.3(GND1) U44.7(EP) U50.4(V-) U53.4(V-) U54.4(GND) U55.4(IN-) U55.5(GND)
GND: C70.1 C71.2 C217.1 C230.1 C232.2 C245.1 C249.1 C266.1 U46.5(GND) U48.2(GND) U49.7(GND) U51.3(GND) U52.2(GND) U55.9(SDI)
VCC: C217.2 C230.2 C232.1 C245.2 C249.2 C266.2 FR9.2 U46.8(VDD) U48.1(VCC) U49.2(D) U49.4(PR) U49.10(PR) U49.12(D) U49.14(VCC) U51.5(VCC) U52.1(VCC)
VDD: U55.10(VIO)  [project net VCCAUX]
VREF-PH: C86.2 C87.2 C89.2 C248.1 R115.2 TP5.1 U50.5(IN+) U53.3(IN+) U54.6(OUT)
ACLK: U55.8(SCK) ; port CLOCK.ACLK  [project net CLOCK.ACLK]
ACNV: U55.6(CNV) ; port CLOCK.ACNV  [project net CLOCK.ACNV]
AIN: U55.7(SDO) ; port CLOCK.AIN  [project net CLOCK.AIN]
CNTROUT_N: U48.4(B) ; port CLOCK.CNTROUT_N  [project net CLOCK.CNTROUT_N]
CNTROUT_P: U48.3(A) ; port CLOCK.CNTROUT_P  [project net CLOCK.CNTROUT_P]
MON: C88.2 R116.2 R117.1 U53.5(IN+)
OSCCLK_N: R95.2 U46.6(Z) ; port CLOCK.OSCCLK_N  [project net CLOCK.OSCCLK_N]
OSCCLK_P: R93.1 U46.7(Y) ; port CLOCK.OSCCLK_P  [project net CLOCK.OSCCLK_P]
SYNC_N: U52.4(B) ; port CLOCK.SYNC_N  [project net CLOCK.SYNC_N]
SYNC_P: U52.3(A) ; port CLOCK.SYNC_P  [project net CLOCK.SYNC_P]
VCOCLK_N: R92.2 R95.1 R97.1 TP40.1 U44.4(Q) U46.3(B)
VCOCLK_P: R91.2 R92.1 R93.2 TP39.1 U44.5(~{Q}) U46.2(A)
VVCO: C64.2 C267.2 FR9.1 R87.2 U44.6(VDD)
NetC61_1: C61.1 C67.2 R102.2
NetC61_2: C61.2 C67.1 R103.2 R116.1 TP6.1 U50.7(OUT)
NetC70_2: C70.2 R108.2 R110.1
NetC71_1: C71.1 R111.1 R113.2
NetC90_1: C90.1 R284.2 U53.1(OUT) U53.2(IN-) U55.1(REF)
NetC198_2: C198.2 R284.1 U55.2(VDD)
NetC215_1: C215.1 R112.2 R292.1 TP7.1 U50.1(OUT)
NetC215_2: C215.2 R111.2 R112.1 U50.2(IN-)
NetC248_2: C248.2 R110.2 R115.1 U50.3(IN+)
NetC272_1: C272.1 R103.1 R303.1 U44.1(VC)
NetR87_1: R87.1 R94.1 U44.2(OE)
NetR102_1: R102.1 R292.2 TP4.1 U50.6(IN-)
NetR108_1: R108.1 U49.9(Q) U51.2
NetR113_1: R113.1 U49.5(Q) U51.1
NetU48_5: U48.5(R) U49.11(CLK)
NetU49_1: U49.1(CLR) U49.13(CLR) U51.4
NetU49_3: U49.3(CLK) U52.5(R)
NetU53_6: U53.6(IN-) U53.7(OUT) U55.3(IN+)

Not connected (* = marked no-connect by the designer): U46 1(NC)* 4(VBB)*; U49 6(~{Q})* 8(~{Q})*; U54 1(NC)* 3(NC)* 5(NC)* 7(NC)* 8(NC)*

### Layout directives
differential pair: VCOCLK_N, VCOCLK_P

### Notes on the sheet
- (near R284) Control Voltage Monitor
- Voltage Legend:
  SW+2V = 2V from switcher
  SW+4V = 4V from switcher
  +/- 7V step down from +/- 10V switcher
  DAC Power
  AVCC_3.3V = Power Reference for DAC
  VCCA_3.3V = Digital Power for DAC
  DVDD_1.2V Core = Digital Core for DAC
  Phase Power:
  +7V Power from front end power.
  VREF-PH = 3.0V Reference for Phase Detector
  FPGA Power:
  AVCC1V8 = XADCVCC
  VCC3V3 = VCC
  VCC2V5 = FPGA 2.5V dpwr LVDS Power
  VCC1V8 = VDD = VCCAUX
  VCC1V0 = VCCINT = VCCBRAM
  VREG = 5.1V Linear from FPGA Power
  PCIe
  AVTT = 1.2V
  AVCC = 1.0V
- Phase Detector
- Vectron VCO
- 3.0V Reference
- (near R95) Optional LVPECL-LVDS Translator

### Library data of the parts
C61 = CapPolypropylene ECQPZ: Polypropylene Film Capacitor, radial lead; Part Number: 399-13063-ND
C64 C86-C88 C196 C217 C230 C245 C249 C266 = ChipCap: as C94 on sheet LD32_XADC
C67 C70 C71 C272 = ChipCap: C0402 1.0nF COG; Part Number: 0402N102J250CT
C89 C195 C198 = ChipCap: as C97 on sheet LD32_XADC
C90 C188 C232 C267 = ChipCap: C0805 10uF; Part Number: CL21A106KAYNNNG
C215 C248 = ChipCap
FR9 = BLM31PG121SN1: as FR1 on sheet LD32_XADC
LOGO2#1 = LIGO_logo
R87 R91-R95 R97 = ChipRes1
R102 R108 R110 R111 R113 R116 R117 = ChipRes1: R0402 10k; Part Number: ERA-2AEB103X
R103 R303 = ChipRes1: R0402 1.0k; Part Number: ERA-2AEB102X
R112 R115 = ChipRes1: R0402 20k; Part Number: RT0402BRD0720KL
R284 = ChipRes1: R0402 10; Part Number: RP73PF1E10RBTD
R292 = ChipRes1: R0402 4.99k; Part Number: RR0510P-4991-D
TP4 TP6 TP7 = TP_SIGNAL: Testpoint, yellow; Part Number: Keystone / 5004
TP5 = TP_POSITIVE: as TP8 on sheet LD32_XADC
TP39 TP40 = TP_SIGNAL: Testpoint,SMD, micro miniature; Part Number: Keystone / 5017
U44 = VCXO_BomarSiTime: Voltage controlled crystal oscillator, differential output, Bomar 14.3 x 8.7mm, or SiTime 7.0 x 5.0mm; Part Number: B1815-BA0S36LK-67.108864
U46 = SN65LVDS100: as U47 on sheet LD32_FLASH
U48 U52 = SN65LVDT2DBV: Single LVDS Receiver with 100 Ohm termination; Part Number: SN65LVDT2DBVR
U49 = 74F74PC: Dual D-Type Positive Edge-Triggered Flip-Flop
U50 U53 = OP284FS: as U57 on sheet LD32_XADC
U51 = SN74LVC1G00: Part Number: 296-9845-1-ND
U54 = ADR292ER: Low-Noise Micropower Precision Voltage Reference; Part Number: ADR4530ARZ-R7
U55 = AD7685: 16 bit ADC, 250kSPS, pseudo differential, serial; Part Number: AD7685BRMZRL7

## Sheet LD32_PCIE_HL.SchDoc: PCIe Interface
size B; SheetNumber: 16; SheetTotal: 17; PageSetup: Record=PageOptions¦CenterHorizontal=True¦CenterVertical=True¦PrintScale=0.72¦XCorrection=1.00¦YCorrection=1.00¦PrintKind=0¦BorderSize=5000000¦LeftOffset=0¦BottomOffset=0¦Orientation=2¦PaperLength=1000¦PaperWidth=1000¦Scale=100¦PaperSource=7¦PrintQuality=-4¦MediaType=1¦DitherType=10¦PaperKind=Tabloid¦PrintScaleMode=1
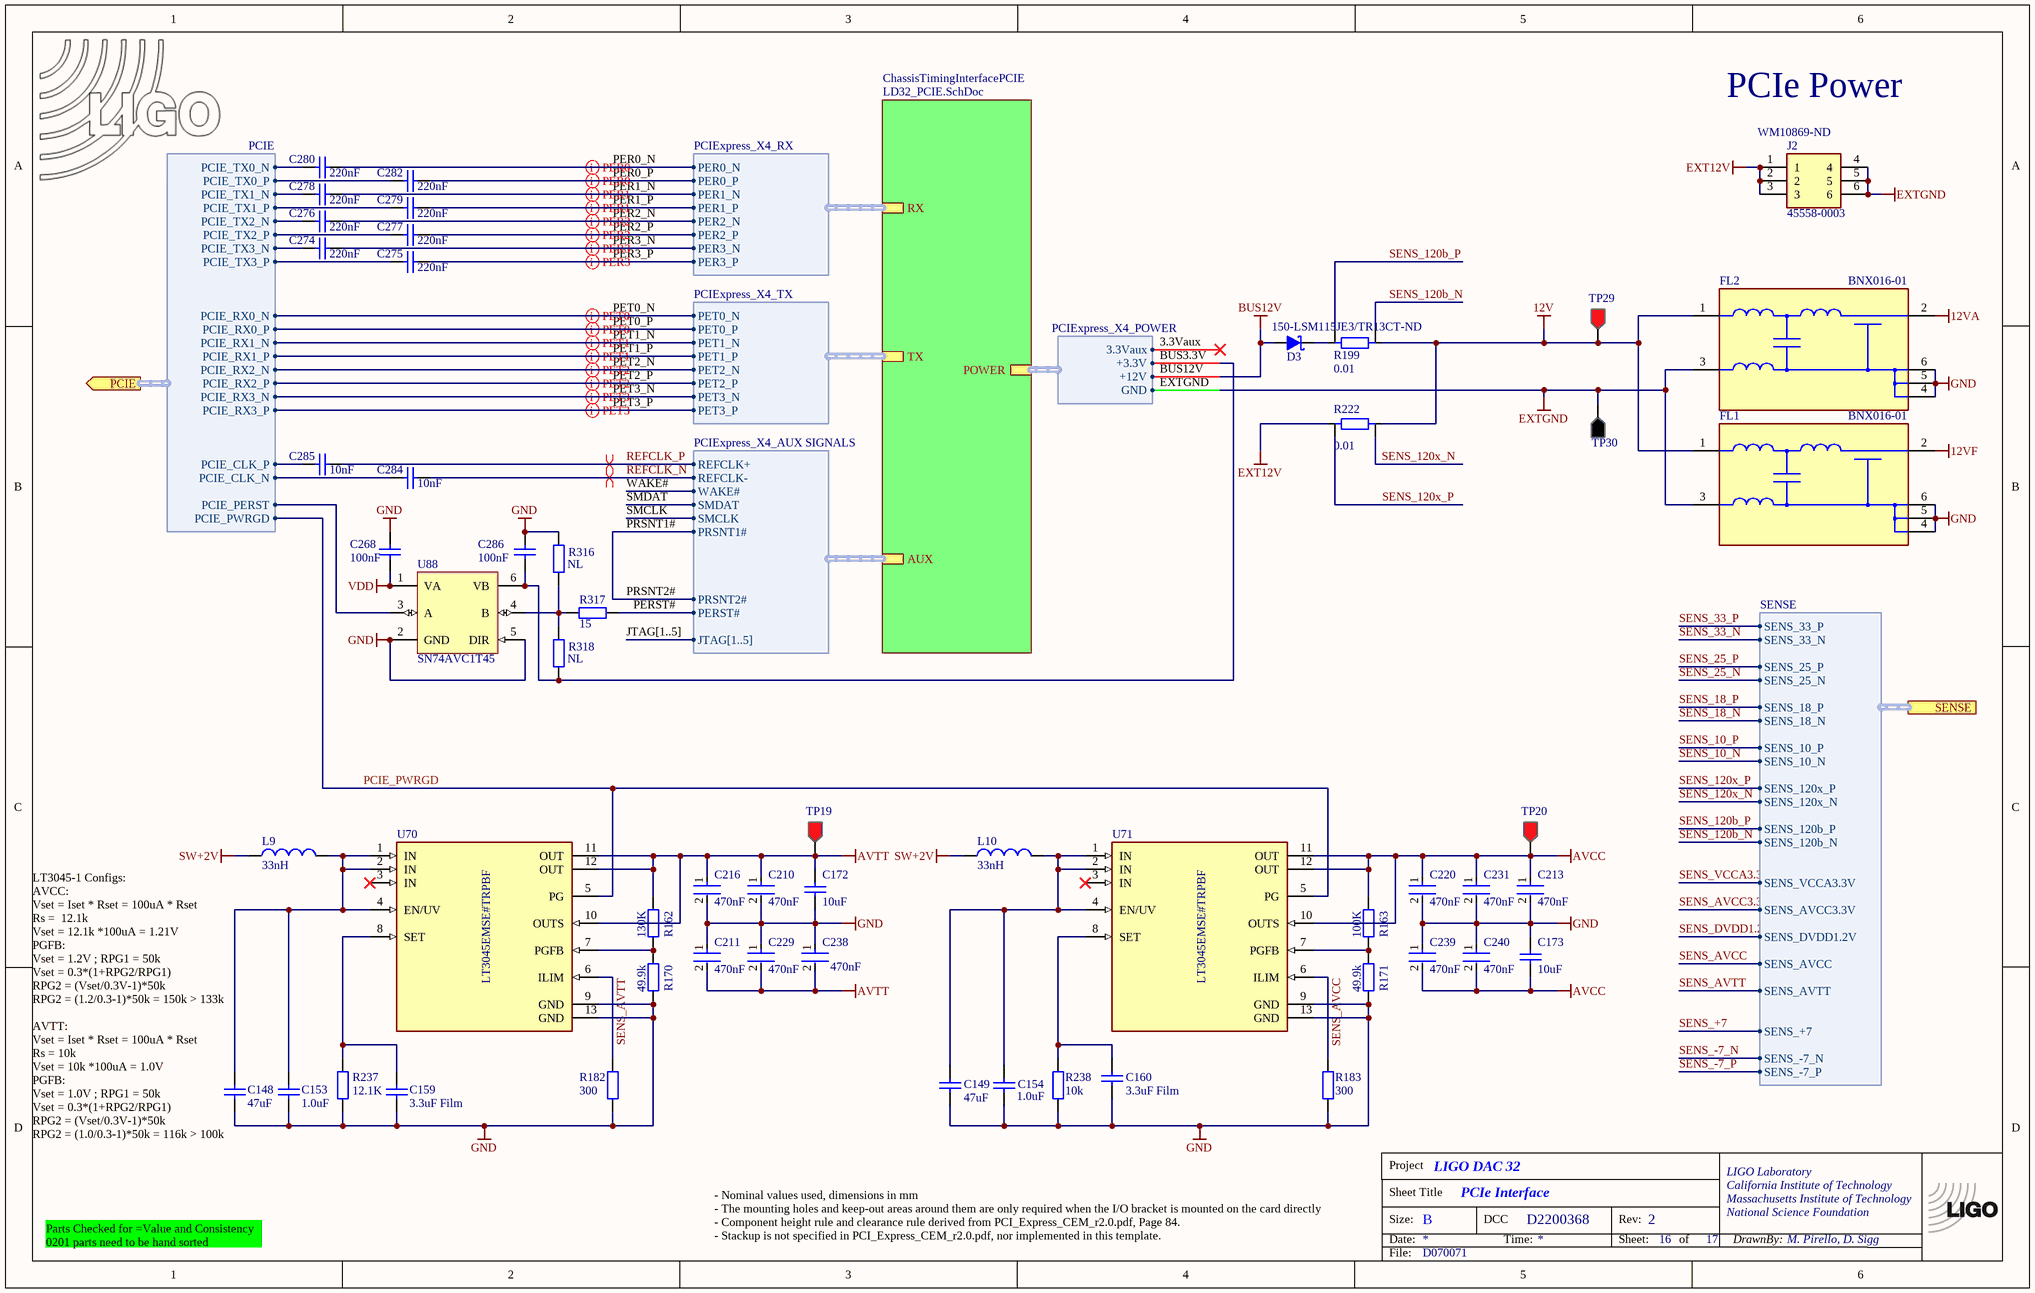
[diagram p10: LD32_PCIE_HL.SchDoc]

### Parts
(Parts that share a designator on the sheet are numbered #1, #2 ... from top to bottom, then left to right.)
*?#7  TitleBlock  (value not drawn)  (graphical)
C148  47uF  [CC3216-1206]
C149  47uF  [CC3216-1206]
C153  1.0uF  [CC1608-0603]
C154  1.0uF  [CC1608-0603]
C159  3.3uF Film  [CC3225-1210]
C160  3.3uF Film  [CC3225-1210]
C172  10uF  [CC2013-0805]
C173  10uF  [CC2013-0805]
C210  470nF  [FP-CL03-IPC_B]
C211  470nF  [FP-CL03-IPC_B]
C213  470nF  [FP-CL03-IPC_B]
C216  470nF  [FP-CL03-IPC_B]
C220  470nF  [FP-CL03-IPC_B]
C229  470nF  [FP-CL03-IPC_B]
C231  470nF  [FP-CL03-IPC_B]
C238  470nF  [FP-CL03-IPC_B]
C239  470nF  [FP-CL03-IPC_B]
C240  470nF  [FP-CL03-IPC_B]
C268  100nF  [CC1005-0402]
C274  220nF  [CC1005-0402]
C275  220nF  [CC1005-0402]
C276  220nF  [CC1005-0402]
C277  220nF  [CC1005-0402]
C278  220nF  [CC1005-0402]
C279  220nF  [CC1005-0402]
C280  220nF  [CC1005-0402]
C282  220nF  [CC1005-0402]
C284  10nF  [CC1005-0402]
C285  10nF  [CC1005-0402]
C286  100nF  [CC1005-0402]
D3  Supplier Part Number 1: 150-LSM115JE3/TR13CT-ND  [DO-SMB]  (hidden comment: Schottky SMB)
FL1  BNX016-01  [FP-BNX_L12MM2_W11MM2_T8MM-MFG]
FL2  BNX016-01  [FP-BNX_L12MM2_W11MM2_T8MM-MFG]
J2  45558-0003  Supplier Part Number 1: WM10869-ND  [455580003]
L9  33nH  [CL2520-1008]
L10  33nH  [CL2520-1008]
LOGO?#2  LIGO logo  [LIGO_LOGO]  (value not drawn)  (graphical)
R162  130K  [CR1005-0402]
R163  100K  [CR1005-0402]
R170  49.9k  [CR1005-0402]
R171  49.9k  [CR1005-0402]
R182  300  [CR1005-0402]
R183  300  [CR1005-0402]
R199  0.01  [CR0816-0306-4P]
R222  0.01  [CR0816-0306-4P]
R237  12.1K  [CR1005-0402]
R238  10k  [CR1005-0402]
R316  NL  [CR1005-0402]
R317  15  [CR1005-0402]
R318  NL  [CR1005-0402]
TP19  Testpoint  [TP1-RED]  (value not drawn)
TP20  Testpoint  [TP1-RED]  (value not drawn)
TP29  Testpoint  [TP1-RED]  (value not drawn)
TP30  Testpoint  [TP1-BLK]  (value not drawn)
U70  LT3045EMSE#TRPBF  [FP-MSE-12-05-08-1666-IPC_B]
U71  LT3045EMSE#TRPBF  [FP-MSE-12-05-08-1666-IPC_B]
U88  SN74AVC1T45  [SO-G6/E2.4]

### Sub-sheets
ChassisTimingInterfacePCIE = LD32_PCIE.SchDoc: RX (harness PCIExpress_X4_RX), TX (harness PCIExpress_X4_TX), AUX (harness PCIExpress_X4_AUX SIGNALS), POWER (harness PCIExpress_X4_POWER)

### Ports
PCIE (out, harness PCIE), SENSE (harness SENSE)

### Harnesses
PCIE: PCIE_CLK_N, PCIE_CLK_P, PCIE_RX0_N, PCIE_RX0_P, PCIE_TX0_N, PCIE_TX0_P, PCIE_PERST, PCIE_PWRGD, PCIE_TX1_N, PCIE_TX1_P, PCIE_TX2_P, PCIE_TX2_N, PCIE_TX3_P, PCIE_TX3_N, PCIE_RX1_N, PCIE_RX1_P, PCIE_RX2_N, PCIE_RX2_P, PCIE_RX3_N, PCIE_RX3_P
PCIExpress_X4_POWER: +3.3V, +12V, GND, 3.3Vaux
PCIExpress_X4_AUX SIGNALS: JTAG[1..5], PERST#, PRSNT1#, PRSNT2#, REFCLK+, REFCLK-, SMCLK, SMDAT, WAKE#
PCIExpress_X4_RX: PER0_N, PER0_P, PER1_N, PER1_P, PER2_N, PER2_P, PER3_N, PER3_P
PCIExpress_X4_TX: PET0_N, PET0_P, PET1_N, PET1_P, PET2_N, PET2_P, PET3_N, PET3_P
SENSE: SENS_33_P, SENS_33_N, SENS_25_P, SENS_25_N, SENS_18_P, SENS_18_N, SENS_10_P, SENS_10_N, SENS_120x_P, SENS_120x_N, SENS_120b_P, SENS_120b_N, SENS_VCCA3.3V, SENS_AVCC3.3V, SENS_DVDD1.2V, SENS_+7, SENS_-7_P, SENS_AVTT, SENS_AVCC, SENS_-7_N

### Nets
12V: FL1.1(B) FL2.1(B) R199.1 R222.4 TP29.1
12VA: FL2.2(CB)
12VF: FL1.2(CB)
AVCC: C173.1 C213.1 C220.1 C231.1 C239.2 C240.2 R163.2 TP20.1 U71.10(OUTS) U71.11(OUT) U71.12(OUT)
AVTT: C172.2 C210.1 C211.2 C216.1 C229.2 C238.2 R162.2 TP19.1 U70.10(OUTS) U70.11(OUT) U70.12(OUT)
BUS3.3V: C286.1 R318.2 U88.6(VB) ; sheet ChassisTimingInterfacePCIE/POWER.+3.3V
BUS12V: D3.1(A) ; sheet ChassisTimingInterfacePCIE/POWER.+12V
EXT12V: J2.1 J2.2 J2.3 R222.1
EXTGND: FL1.3(PSG) FL2.3(PSG) J2.4 J2.5 J2.6 TP30.1 ; sheet ChassisTimingInterfacePCIE/POWER.GND
GND: C148.1 C149.1 C153.1 C154.1 C159.1 C160.1 C172.1 C173.2 C210.2 C211.1 C213.2 C216.2 C220.2 C229.1 C231.2 C238.1 C239.1 C240.1 C268.2 C286.2 FL1.4(CG) FL1.5(CG) FL1.6(CG) FL2.4(CG) FL2.5(CG) FL2.6(CG) R170.1 R171.1 R182.1 R183.1 R237.1 R238.1 R316.1 U70.9(GND) U70.13(GND) U71.9(GND) U71.13(GND) U88.2(GND) U88.5(DIR)
SENS_18_N: C268.1 U88.1(VA) ; port SENSE.SENS_18_N  [also labelled VDD]  [project net VCCAUX]
SW+2V: L9.1 L10.1
PCIE.PCIE_CLK_N: C284.2 ; port PCIE.PCIE_CLK_N
PCIE.PCIE_CLK_P: C285.2 ; port PCIE.PCIE_CLK_P
PCIE.PCIE_PERST: U88.3(A) ; port PCIE.PCIE_PERST
PCIE.PCIE_TX0_N: C280.2 ; port PCIE.PCIE_TX0_N
PCIE.PCIE_TX0_P: C282.2 ; port PCIE.PCIE_TX0_P
PCIE.PCIE_TX1_N: C278.2 ; port PCIE.PCIE_TX1_N
PCIE.PCIE_TX1_P: C279.2 ; port PCIE.PCIE_TX1_P
PCIE.PCIE_TX2_N: C276.2 ; port PCIE.PCIE_TX2_N
PCIE.PCIE_TX2_P: C277.2 ; port PCIE.PCIE_TX2_P
PCIE.PCIE_TX3_N: C274.2 ; port PCIE.PCIE_TX3_N
PCIE.PCIE_TX3_P: C275.2 ; port PCIE.PCIE_TX3_P
PCIE_PWRGD: U70.5(PG) U71.5(PG) ; port PCIE.PCIE_PWRGD  [project net PCIE.PCIE_PWRGD]
PER0_N: C280.1 ; sheet ChassisTimingInterfacePCIE/RX.PER0_N
PER0_P: C282.1 ; sheet ChassisTimingInterfacePCIE/RX.PER0_P
PER1_N: C278.1 ; sheet ChassisTimingInterfacePCIE/RX.PER1_N
PER1_P: C279.1 ; sheet ChassisTimingInterfacePCIE/RX.PER1_P
PER2_N: C276.1 ; sheet ChassisTimingInterfacePCIE/RX.PER2_N
PER2_P: C277.1 ; sheet ChassisTimingInterfacePCIE/RX.PER2_P
PER3_N: C274.1 ; sheet ChassisTimingInterfacePCIE/RX.PER3_N
PER3_P: C275.1 ; sheet ChassisTimingInterfacePCIE/RX.PER3_P
PERST#: R317.1 ; sheet ChassisTimingInterfacePCIE/AUX.PERST#
PET0_N: port PCIE.PCIE_RX0_N, sheet ChassisTimingInterfacePCIE/TX.PET0_N  [project net PCIE.PCIE_RX0_N]
PET0_P: port PCIE.PCIE_RX0_P, sheet ChassisTimingInterfacePCIE/TX.PET0_P  [project net PCIE.PCIE_RX0_P]
PET1_N: port PCIE.PCIE_RX1_N, sheet ChassisTimingInterfacePCIE/TX.PET1_N  [project net PCIE.PCIE_RX1_N]
PET1_P: port PCIE.PCIE_RX1_P, sheet ChassisTimingInterfacePCIE/TX.PET1_P  [project net PCIE.PCIE_RX1_P]
PET2_N: port PCIE.PCIE_RX2_N, sheet ChassisTimingInterfacePCIE/TX.PET2_N  [project net PCIE.PCIE_RX2_N]
PET2_P: port PCIE.PCIE_RX2_P, sheet ChassisTimingInterfacePCIE/TX.PET2_P  [project net PCIE.PCIE_RX2_P]
PET3_N: port PCIE.PCIE_RX3_N, sheet ChassisTimingInterfacePCIE/TX.PET3_N  [project net PCIE.PCIE_RX3_N]
PET3_P: port PCIE.PCIE_RX3_P, sheet ChassisTimingInterfacePCIE/TX.PET3_P  [project net PCIE.PCIE_RX3_P]
PRSNT1#: sheet ChassisTimingInterfacePCIE/AUX.PRSNT1#, sheet ChassisTimingInterfacePCIE/AUX.PRSNT2#  [also labelled PRSNT2#]
REFCLK_N: C284.1 ; sheet ChassisTimingInterfacePCIE/AUX.REFCLK-
REFCLK_P: C285.1 ; sheet ChassisTimingInterfacePCIE/AUX.REFCLK+
SENS_120b_N: R199.2 ; port SENSE.SENS_120b_N  [project net SENSE.SENS_120b_N]
SENS_120b_P: R199.3 ; port SENSE.SENS_120b_P  [project net SENSE.SENS_120b_P]
SENS_120x_N: R222.3 ; port SENSE.SENS_120x_N  [project net SENSE.SENS_120x_N]
SENS_120x_P: R222.2 ; port SENSE.SENS_120x_P  [project net SENSE.SENS_120x_P]
SENS_AVCC: R183.2 U71.6(ILIM) ; port SENSE.SENS_AVCC  [project net SENSE.SENS_AVCC]
SENS_AVTT: R182.2 U70.6(ILIM) ; port SENSE.SENS_AVTT  [project net SENSE.SENS_AVTT]
NetC148_2: C148.2 C153.2 L9.2 U70.1(IN) U70.2(IN) U70.4(EN/UV)
NetC149_2: C149.2 C154.2 L10.2 U71.1(IN) U71.2(IN) U71.4(EN/UV)
NetC159_2: C159.2 R237.2 U70.8(SET)
NetC160_2: C160.2 R238.2 U71.8(SET)
NetD3_2: D3.2(K) R199.4
NetR162_1: R162.1 R170.2 U70.7(PGFB)
NetR163_1: R163.1 R171.2 U71.7(PGFB)
NetR316_2: R316.2 R317.2 R318.1 U88.4(B)

Not connected (* = marked no-connect by the designer): U70 3(IN)*; U71 3(IN)*

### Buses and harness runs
bus JTAG[1..5]

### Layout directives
differential pair: PCIE.PCIE_RX0_N, PCIE.PCIE_RX0_P, PCIE.PCIE_RX1_N, PCIE.PCIE_RX1_P, PCIE.PCIE_RX2_N, PCIE.PCIE_RX2_P, PCIE.PCIE_RX3_N, PCIE.PCIE_RX3_P, PER0_N, PER0_P, PER1_N, PER1_P, PER2_N, PER2_P, PER3_N, PER3_P, REFCLK_N, REFCLK_P

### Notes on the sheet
- PCIe Power
- (near C148) LT3045-1 Configs:
  AVCC:
  Vset = Iset * Rset = 100uA * Rset
  Rs =  12.1k
  Vset = 12.1k *100uA = 1.21V
  PGFB:
  Vset = 1.2V ; RPG1 = 50k
  Vset = 0.3*(1+RPG2/RPG1)
  RPG2 = (Vset/0.3V-1)*50k
  RPG2 = (1.2/0.3-1)*50k = 150k > 133k
  AVTT:
  Vset = Iset * Rset = 100uA * Rset
  Rs = 10k
  Vset = 10k *100uA = 1.0V
  PGFB:
  Vset = 1.0V ; RPG1 = 50k
  Vset = 0.3*(1+RPG2/RPG1)
  RPG2 = (Vset/0.3V-1)*50k
  RPG2 = (1.0/0.3-1)*50k = 116k > 100k
- Parts Checked for =Value and Consistency
  0201 parts need to be hand sorted
- (near *?#7) - Nominal values used, dimensions in mm
  - The mounting holes and keep-out areas around them are only required when the I/O bracket is mounted on the card directly
  - Component height rule and clearance rule derived from PCI_Express_CEM_r2.0.pdf, Page 84.
  - Stackup is not specified in PCI_Express_CEM_r2.0.pdf, nor implemented in this template.

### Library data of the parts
C148 C149 = ChipCap: C1206 47uF; Part Number: C3216X5R1E476M160DC
C153 C154 = ChipCap: as C97 on sheet LD32_XADC
C159 C160 = ChipCap: C1210 3.3uF Film; Part Number: 16MU335MB33225
C172 C173 = ChipCap: C0805 10uF; Part Number: CL21A106KAYNNNG
C210 C211 C213 C216 C220 C229 C231 C238-C240 = CMP-2010-00306-2: Cap Ceramic 470nF 4V X5R ±20% Pad SMD 0201 +85°C T/R; Part Number: LMK063BBJ474MPLF
C268 C286 = ChipCap: as C94 on sheet LD32_XADC
C274-C280 C282 = ChipCap: C0402 0.22uF; Part Number: TMK105B7224KV-FR
C284 C285 = ChipCap: as C69 on sheet LD32_FLASH
D3 = DIODE_SHOTTKY: Part Number: LSM115JE3/TR13
FL1 FL2 = CMP-2000-05960-2: FILTER LC TH
J2 = 45558-0003: Connector
L9 = ChipInductor: Inductor; Part Number: 994-1008CS-330XGLC
L10 = ChipInductor: Inductor; Part Number: 994-1008CS-101XJLC
LOGO?#2 = LIGO_logo
R162 = ChipRes1: R0402 130k; Part Number: RP73PF1E130KBTD
R163 = ChipRes1: R0402 100k; Part Number: ERA-2AEB104X
R170 R171 = ChipRes1: R0402 49.9k; Part Number: RR0510P-4992-D
R182 R183 = ChipRes1: R0402 300; Part Number: RR05P300DCT-ND
R199 R222 = RW1S0CK: Four-Terminal Current Sense Resistor; Part Number: FC4L16R010FER
R237 = ChipRes1: R0402 12.1k; Part Number: ERA-2AEB1212X
R238 = ChipRes1: R0402 10k; Part Number: ERA-2AEB103X
R316 R318 = ChipRes1
R317 = ChipRes1: R0402 15; Part Number: RP73PF1E15RBTD
TP19 TP20 TP29 = TP_POSITIVE: as TP8 on sheet LD32_XADC
TP30 = TP_GND: Testpoint, black; Part Number: Keystone / 5001
U70 U71 = CMP-09138-000053-1: IC REG LINEAR 0V 500MA 12MSOP; Part Number: LT3045EMSE-1#PBF
U88 = SN74LVC1T45: Single-Bit Dual Supply Transceiver; Part Number: SN74AVC1T45DBVT

## Sheet LD32_PCIE.SchDoc: PCIe
size B; SheetNumber: 17; SheetTotal: 17; PageSetup: Record=PageOptions¦CenterHorizontal=True¦CenterVertical=True¦PrintScale=0.72¦XCorrection=1.00¦YCorrection=1.00¦PrintKind=0¦BorderSize=5000000¦LeftOffset=0¦BottomOffset=0¦Orientation=2¦PaperLength=1000¦PaperWidth=1000¦Scale=100¦PaperSource=7¦PrintQuality=-4¦MediaType=1¦DitherType=10¦PaperKind=Tabloid¦PrintScaleMode=1
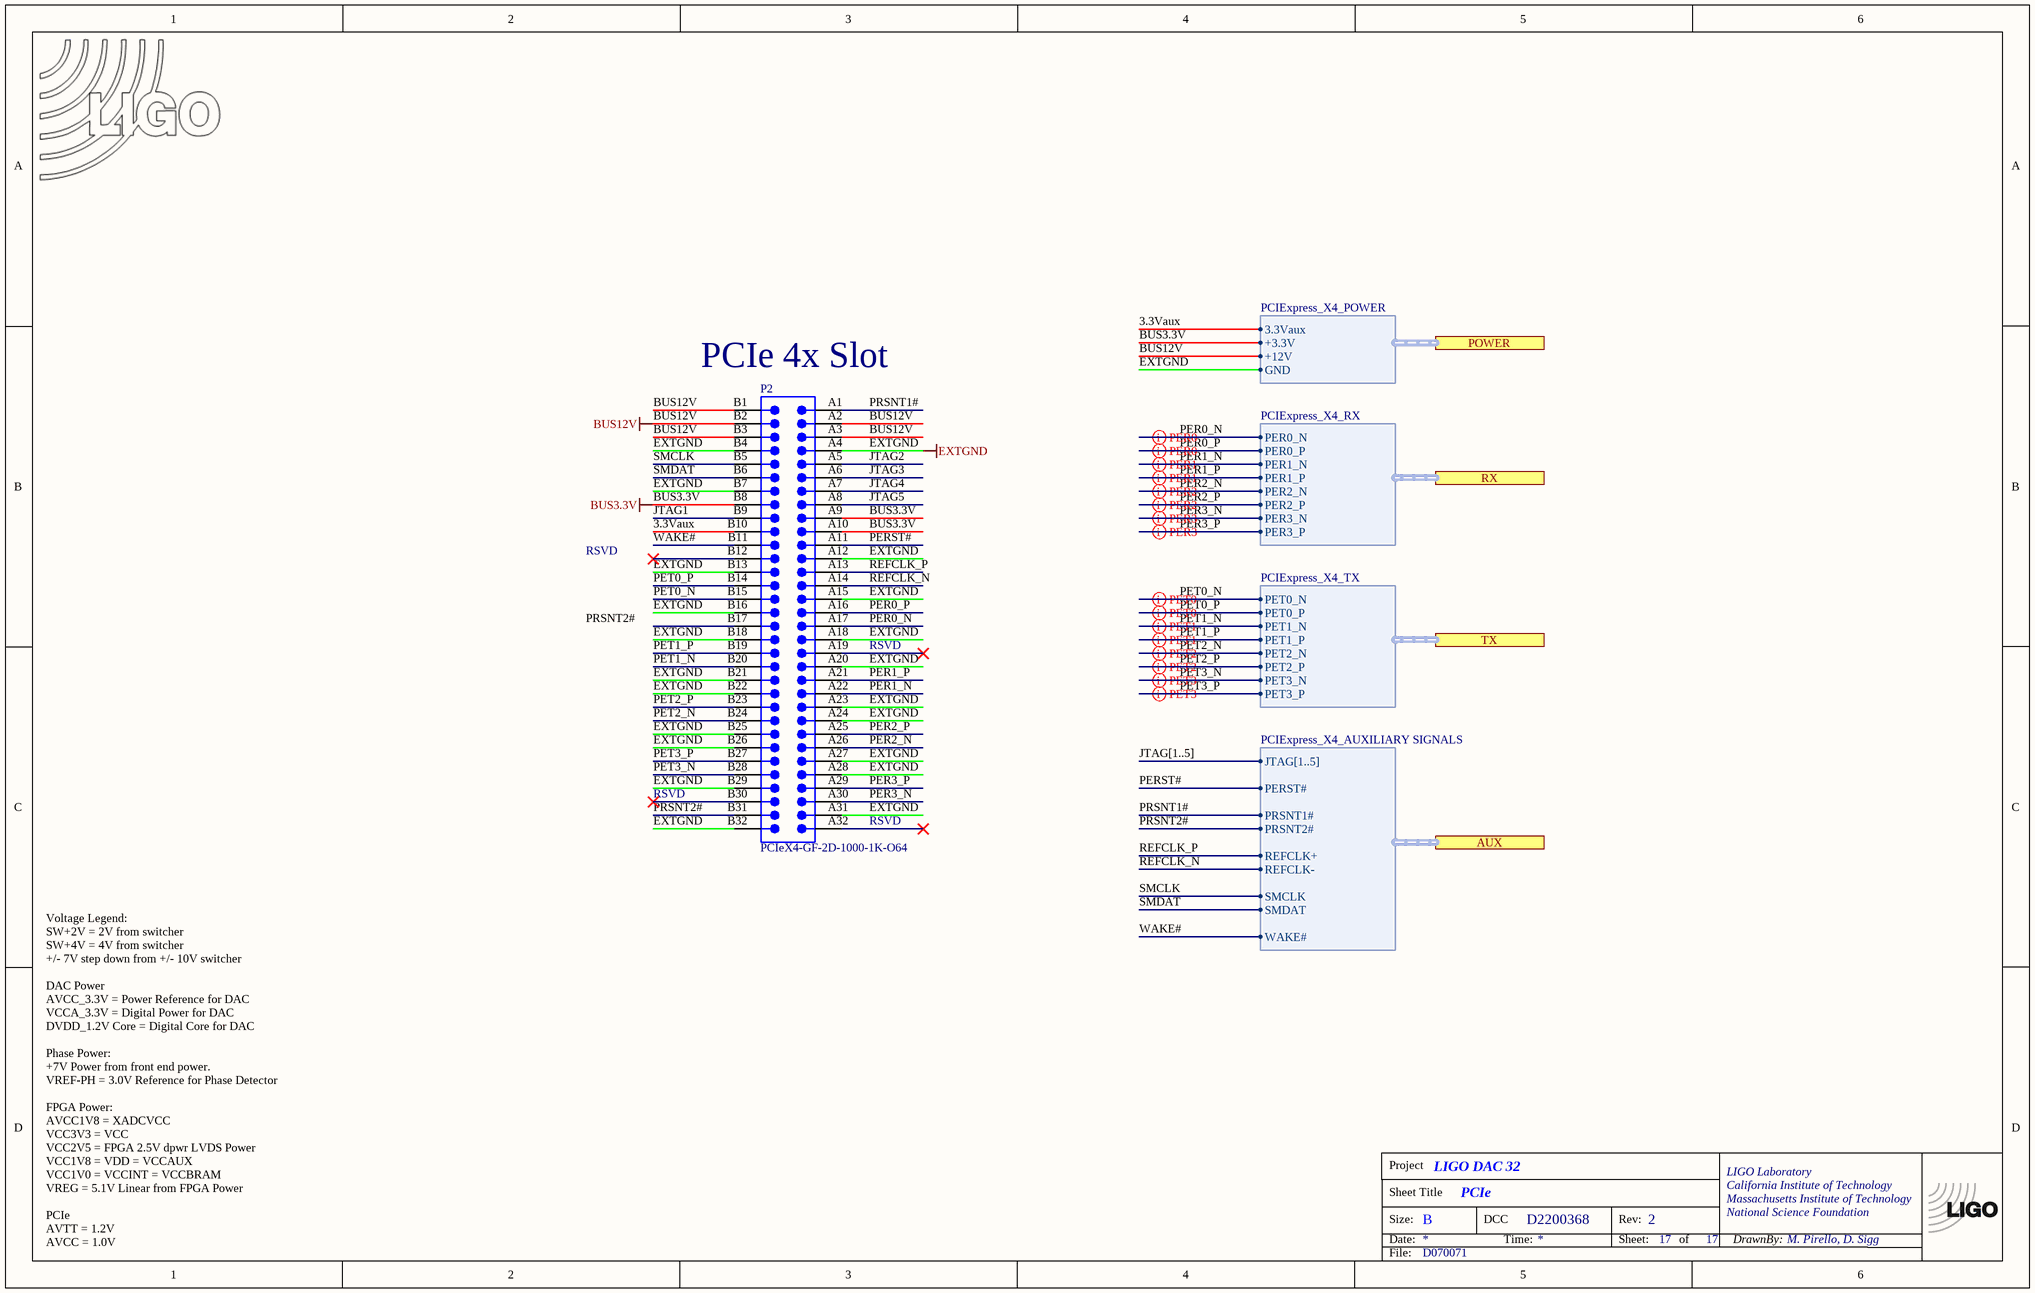
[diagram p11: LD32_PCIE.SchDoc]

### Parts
(Parts that share a designator on the sheet are numbered #1, #2 ... from top to bottom, then left to right.)
*?#8  TitleBlock  (value not drawn)  (graphical)
LOGO?#3  LIGO logo  [LIGO_LOGO]  (value not drawn)  (graphical)
P2  PCIeX4-GF-2D-1000-1K-O64  [PCIeX4-GF-2D-1000-1K-O64]  (no BOM)

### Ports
AUX (harness PCIExpress_X4_AUXILIARY SIGNALS), POWER (harness PCIExpress_X4_POWER), RX (harness PCIExpress_X4_RX), TX (harness PCIExpress_X4_TX)

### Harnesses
PCIExpress_X4_RX: PER0_N, PER0_P, PER1_N, PER1_P, PER2_N, PER2_P, PER3_N, PER3_P
PCIExpress_X4_TX: PET0_N, PET0_P, PET1_N, PET1_P, PET2_N, PET2_P, PET3_N, PET3_P
PCIExpress_X4_POWER: +3.3V, +12V, GND, 3.3Vaux
PCIExpress_X4_AUXILIARY SIGNALS: JTAG[1..5], PERST#, PRSNT1#, PRSNT2#, REFCLK+, REFCLK-, SMCLK, SMDAT, WAKE#

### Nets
BUS3.3V: P2.A9 P2.A10 P2.B8 ; port POWER.+3.3V
BUS12V: P2.A2 P2.A3 P2.B1 P2.B2 P2.B3 ; port POWER.+12V
EXTGND: P2.A4 P2.A12 P2.A15 P2.A18 P2.A20 P2.A23 P2.A24 P2.A27 P2.A28 P2.A31 P2.B4 P2.B7 P2.B13 P2.B16 P2.B18 P2.B21 P2.B22 P2.B25 P2.B26 P2.B29 P2.B32 ; port POWER.GND
3.3Vaux: P2.B10 ; port POWER.3.3Vaux
JTAG1: P2.B9
JTAG2: P2.A5
JTAG3: P2.A6
JTAG4: P2.A7
JTAG5: P2.A8
PER0_N: P2.A17 ; port RX.PER0_N
PER0_P: P2.A16 ; port RX.PER0_P
PER1_N: P2.A22 ; port RX.PER1_N
PER1_P: P2.A21 ; port RX.PER1_P
PER2_N: P2.A26 ; port RX.PER2_N
PER2_P: P2.A25 ; port RX.PER2_P
PER3_N: P2.A30 ; port RX.PER3_N
PER3_P: P2.A29 ; port RX.PER3_P
PERST#: P2.A11 ; port AUX.PERST#
PET0_N: P2.B15 ; port TX.PET0_N  [project net PCIE.PCIE_RX0_N]
PET0_P: P2.B14 ; port TX.PET0_P  [project net PCIE.PCIE_RX0_P]
PET1_N: P2.B20 ; port TX.PET1_N  [project net PCIE.PCIE_RX1_N]
PET1_P: P2.B19 ; port TX.PET1_P  [project net PCIE.PCIE_RX1_P]
PET2_N: P2.B24 ; port TX.PET2_N  [project net PCIE.PCIE_RX2_N]
PET2_P: P2.B23 ; port TX.PET2_P  [project net PCIE.PCIE_RX2_P]
PET3_N: P2.B28 ; port TX.PET3_N  [project net PCIE.PCIE_RX3_N]
PET3_P: P2.B27 ; port TX.PET3_P  [project net PCIE.PCIE_RX3_P]
PRSNT1#: P2.A1 P2.B31 ; port AUX.PRSNT1#, port AUX.PRSNT2#  [also labelled PRSNT2#]
REFCLK_N: P2.A14 ; port AUX.REFCLK-
REFCLK_P: P2.A13 ; port AUX.REFCLK+
SMCLK: P2.B5 ; port AUX.SMCLK
SMDAT: P2.B6 ; port AUX.SMDAT
WAKE#: P2.B11 ; port AUX.WAKE#

Not connected (* = marked no-connect by the designer): P2 A19* A32* B12* B17 B30*

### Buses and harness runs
bus JTAG[1..5]

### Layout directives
differential pair: PCIE.PCIE_RX0_N, PCIE.PCIE_RX0_P, PCIE.PCIE_RX1_N, PCIE.PCIE_RX1_P, PCIE.PCIE_RX2_N, PCIE.PCIE_RX2_P, PCIE.PCIE_RX3_N, PCIE.PCIE_RX3_P, PER0_N, PER0_P, PER1_N, PER1_P, PER2_N, PER2_P, PER3_N, PER3_P

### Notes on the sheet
- (near P2) PCIe 4x Slot
- RSVD
- Voltage Legend:
  SW+2V = 2V from switcher
  SW+4V = 4V from switcher
  +/- 7V step down from +/- 10V switcher
  DAC Power
  AVCC_3.3V = Power Reference for DAC
  VCCA_3.3V = Digital Power for DAC
  DVDD_1.2V Core = Digital Core for DAC
  Phase Power:
  +7V Power from front end power.
  VREF-PH = 3.0V Reference for Phase Detector
  FPGA Power:
  AVCC1V8 = XADCVCC
  VCC3V3 = VCC
  VCC2V5 = FPGA 2.5V dpwr LVDS Power
  VCC1V8 = VDD = VCCAUX
  VCC1V0 = VCCINT = VCCBRAM
  VREG = 5.1V Linear from FPGA Power
  PCIe
  AVTT = 1.2V
  AVCC = 1.0V
- Labels drawn without touching a wire or pin: PRSNT2#

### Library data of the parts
LOGO?#3 = LIGO_logo
P2 = CMP-0001-00031-2: NL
